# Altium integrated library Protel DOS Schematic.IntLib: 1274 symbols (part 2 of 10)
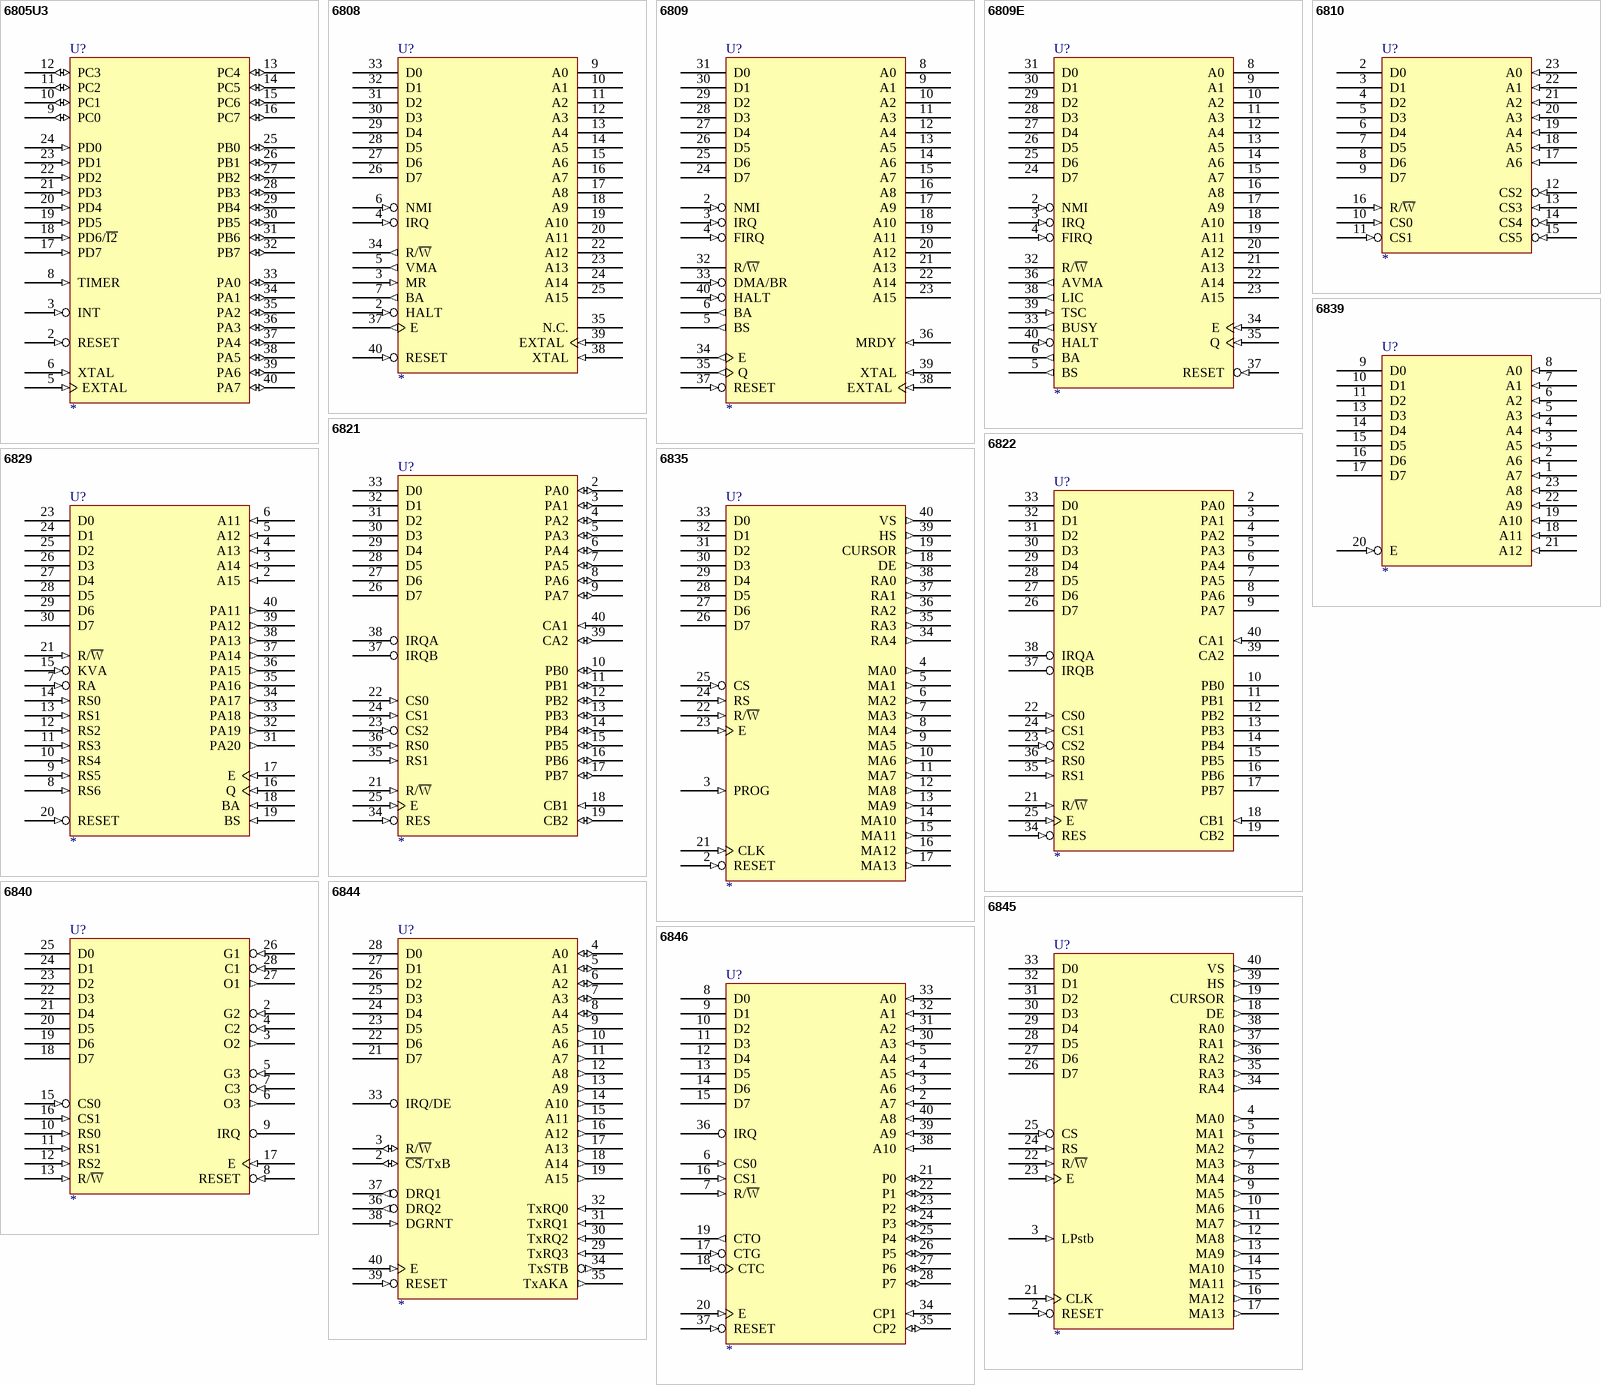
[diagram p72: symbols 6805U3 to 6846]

## 6810
designator U?
footprint DIP-24
pins: 1 GND (power) hidden to GND, 2 D0 (hiz), 3 D1 (hiz), 4 D2 (hiz), 5 D3 (hiz), 6 D4 (hiz), 7 D5 (hiz), 8 D6 (hiz), 9 D7 (hiz), 10 CS0 (in), 11 CS1 (in), 12 CS2 (in), 13 CS3 (in), 14 CS4 (in), 15 CS5 (in), 16 R/~{W} (in), 17 A6 (in), 18 A5 (in), 19 A4 (in), 20 A3 (in), 21 A2 (in), 22 A1 (in), 23 A0 (in), 24 VCC (power) hidden to VCC
2 alternate drawings of the same symbol

## 6821
designator U?
footprint DIP-40
pins: 1 GND (power) hidden to GND, 2 PA0 (io), 3 PA1 (io), 4 PA2 (io), 5 PA3 (io), 6 PA4 (io), 7 PA5 (io), 8 PA6 (io), 9 PA7 (io), 10 PB0 (io), 11 PB1 (io), 12 PB2 (io), 13 PB3 (io), 14 PB4 (io), 15 PB5 (io), 16 PB6 (io), 17 PB7 (io), 18 CB1 (in), 19 CB2 (io), 20 VCC (power) hidden to VCC, 21 R/~{W} (in), 22 CS0 (in), 23 CS2 (in), 24 CS1 (in), 25 E (in), 26 D7 (hiz), 27 D6 (hiz), 28 D5 (hiz), 29 D4 (hiz), 30 D3 (hiz), 31 D2 (hiz), 32 D1 (hiz), 33 D0 (hiz), 34 RES (in), 35 RS1 (in), 36 RS0 (in), 37 IRQB (oc), 38 IRQA (oc), 39 CA2 (io), 40 CA1 (in)
2 alternate drawings of the same symbol

## 6822
designator U?
footprint DIP-40
pins: 1 GND (power) hidden to GND, 2 PA0 (oc), 3 PA1 (oc), 4 PA2 (oc), 5 PA3 (oc), 6 PA4 (oc), 7 PA5 (oc), 8 PA6 (oc), 9 PA7 (oc), 10 PB0 (oc), 11 PB1 (oc), 12 PB2 (oc), 13 PB3 (oc), 14 PB4 (oc), 15 PB5 (oc), 16 PB6 (oc), 17 PB7 (oc), 18 CB1 (in), 19 CB2 (oc), 20 VCC (power) hidden to VCC, 21 R/~{W} (in), 22 CS0 (in), 23 CS2 (in), 24 CS1 (in), 25 E (in), 26 D7 (hiz), 27 D6 (hiz), 28 D5 (hiz), 29 D4 (hiz), 30 D3 (hiz), 31 D2 (hiz), 32 D1 (hiz), 33 D0 (hiz), 34 RES (in), 35 RS1 (in), 36 RS0 (in), 37 IRQB (oc), 38 IRQA (oc), 39 CA2 (oc), 40 CA1 (in)
2 alternate drawings of the same symbol

## 6829
designator U?
footprint DIP-40
pins: 1 GND (power) hidden to GND, 2 A15 (in), 3 A14 (in), 4 A13 (in), 5 A12 (in), 6 A11 (in), 7 RA (in), 8 RS6 (in), 9 RS5 (in), 10 RS4 (in), 11 RS3 (in), 12 RS2 (in), 13 RS1 (in), 14 RS0 (in), 15 KVA (in), 16 Q (in), 17 E (in), 18 BA (in), 19 BS (in), 20 RESET (in), 21 R/~{W} (in), 22 VCC (power) hidden to VCC, 23 D0 (hiz), 24 D1 (hiz), 25 D2 (hiz), 26 D3 (hiz), 27 D4 (hiz), 28 D5 (hiz), 29 D6 (hiz), 30 D7 (hiz), 31 PA20 (out), 32 PA19 (out), 33 PA18 (out), 34 PA17 (out), 35 PA16 (out), 36 PA15 (out), 37 PA14 (out), 38 PA13 (out), 39 PA12 (out), 40 PA11 (out)
2 alternate drawings of the same symbol

## 6835
designator U?
footprint DIP-40
pins: 1 GND (power) hidden to GND, 2 RESET (in), 3 PROG (in), 4 MA0 (out), 5 MA1 (out), 6 MA2 (out), 7 MA3 (out), 8 MA4 (out), 9 MA5 (out), 10 MA6 (out), 11 MA7 (out), 12 MA8 (out), 13 MA9 (out), 14 MA10 (out), 15 MA11 (out), 16 MA12 (out), 17 MA13 (out), 18 DE (out), 19 CURSOR (out), 20 VCC (power) hidden to VCC, 21 CLK (in), 22 R/~{W} (in), 23 E (in), 24 RS (in), 25 CS (in), 26 D7 (hiz), 27 D6 (hiz), 28 D5 (hiz), 29 D4 (hiz), 30 D3 (hiz), 31 D2 (hiz), 32 D1 (hiz), 33 D0 (hiz), 34 RA4 (out), 35 RA3 (out), 36 RA2 (out), 37 RA1 (out), 38 RA0 (out), 39 HS (out), 40 VS (out)
2 alternate drawings of the same symbol

## 6839
designator U?
footprint DIP-24
pins: 1 A7 (in), 2 A6 (in), 3 A5 (in), 4 A4 (in), 5 A3 (in), 6 A2 (in), 7 A1 (in), 8 A0 (in), 9 D0 (hiz), 10 D1 (hiz), 11 D2 (hiz), 12 GND (power) hidden to GND, 13 D3 (hiz), 14 D4 (hiz), 15 D5 (hiz), 16 D6 (hiz), 17 D7 (hiz), 18 A11 (in), 19 A10 (in), 20 E (in), 21 A12 (in), 22 A9 (in), 23 A8 (in), 24 VCC (power) hidden to VCC
2 alternate drawings of the same symbol

## 6840
designator U?
footprint DIP-28
pins: 1 GND (power) hidden to GND, 2 G2 (in), 3 O2 (out), 4 C2 (in), 5 G3 (in), 6 O3 (out), 7 C3 (in), 8 RESET (in), 9 IRQ (oc), 10 RS0 (in), 11 RS1 (in), 12 RS2 (in), 13 R/~{W} (in), 14 VCC (power) hidden to VCC, 15 CS0 (in), 16 CS1 (in), 17 E (in), 18 D7 (hiz), 19 D6 (hiz), 20 D5 (hiz), 21 D4 (hiz), 22 D3 (hiz), 23 D2 (hiz), 24 D1 (hiz), 25 D0 (hiz), 26 G1 (in), 27 O1 (out), 28 C1 (in)
2 alternate drawings of the same symbol

## 6844
designator U?
footprint DIP-40
pins: 1 GND (power) hidden to GND, 2 ~{CS}/TxB (io), 3 R/~{W} (io), 4 A0 (io), 5 A1 (io), 6 A2 (io), 7 A3 (io), 8 A4 (io), 9 A5 (out), 10 A6 (out), 11 A7 (out), 12 A8 (out), 13 A9 (out), 14 A10 (out), 15 A11 (out), 16 A12 (out), 17 A13 (out), 18 A14 (out), 19 A15 (out), 20 VCC (power) hidden to VCC, 21 D7 (hiz), 22 D6 (hiz), 23 D5 (hiz), 24 D4 (hiz), 25 D3 (hiz), 26 D2 (hiz), 27 D1 (hiz), 28 D0 (hiz), 29 TxRQ3 (in), 30 TxRQ2 (in), 31 TxRQ1 (in), 32 TxRQ0 (in), 33 IRQ/DE (oc), 34 TxSTB (out), 35 TxAKA (out), 36 DRQ2 (out), 37 DRQ1 (out), 38 DGRNT (in), 39 RESET (in), 40 E (in)
2 alternate drawings of the same symbol

## 6845
designator U?
footprint DIP-40
pins: 1 GND (power) hidden to GND, 2 RESET (in), 3 LPstb (in), 4 MA0 (out), 5 MA1 (out), 6 MA2 (out), 7 MA3 (out), 8 MA4 (out), 9 MA5 (out), 10 MA6 (out), 11 MA7 (out), 12 MA8 (out), 13 MA9 (out), 14 MA10 (out), 15 MA11 (out), 16 MA12 (out), 17 MA13 (out), 18 DE (out), 19 CURSOR (out), 20 VCC (power) hidden to VCC, 21 CLK (in), 22 R/~{W} (in), 23 E (in), 24 RS (in), 25 CS (in), 26 D7 (hiz), 27 D6 (hiz), 28 D5 (hiz), 29 D4 (hiz), 30 D3 (hiz), 31 D2 (hiz), 32 D1 (hiz), 33 D0 (hiz), 34 RA4 (out), 35 RA3 (out), 36 RA2 (out), 37 RA1 (out), 38 RA0 (out), 39 HS (out), 40 VS (out)
2 alternate drawings of the same symbol

## 6846
designator U?
footprint DIP-40
pins: 1 GND (power) hidden to GND, 2 A7 (in), 3 A6 (in), 4 A5 (in), 5 A4 (in), 6 CS0 (in), 7 R/~{W} (in), 8 D0 (hiz), 9 D1 (hiz), 10 D2 (hiz), 11 D3 (hiz), 12 D4 (hiz), 13 D5 (hiz), 14 D6 (hiz), 15 D7 (hiz), 16 CS1 (in), 17 CTG (in), 18 CTC (in), 19 CTO (out), 20 E (in), 21 P0 (io), 22 P1 (io), 23 P2 (io), 24 P3 (io), 25 P4 (io), 26 P5 (io), 27 P6 (io), 28 P7 (io), 29 VCC (power) hidden to VCC, 30 A3 (in), 31 A2 (in), 32 A1 (in), 33 A0 (in), 34 CP1 (in), 35 CP2 (io), 36 IRQ (oc), 37 RESET (in), 38 A10 (in), 39 A9 (in), 40 A8 (in)
2 alternate drawings of the same symbol

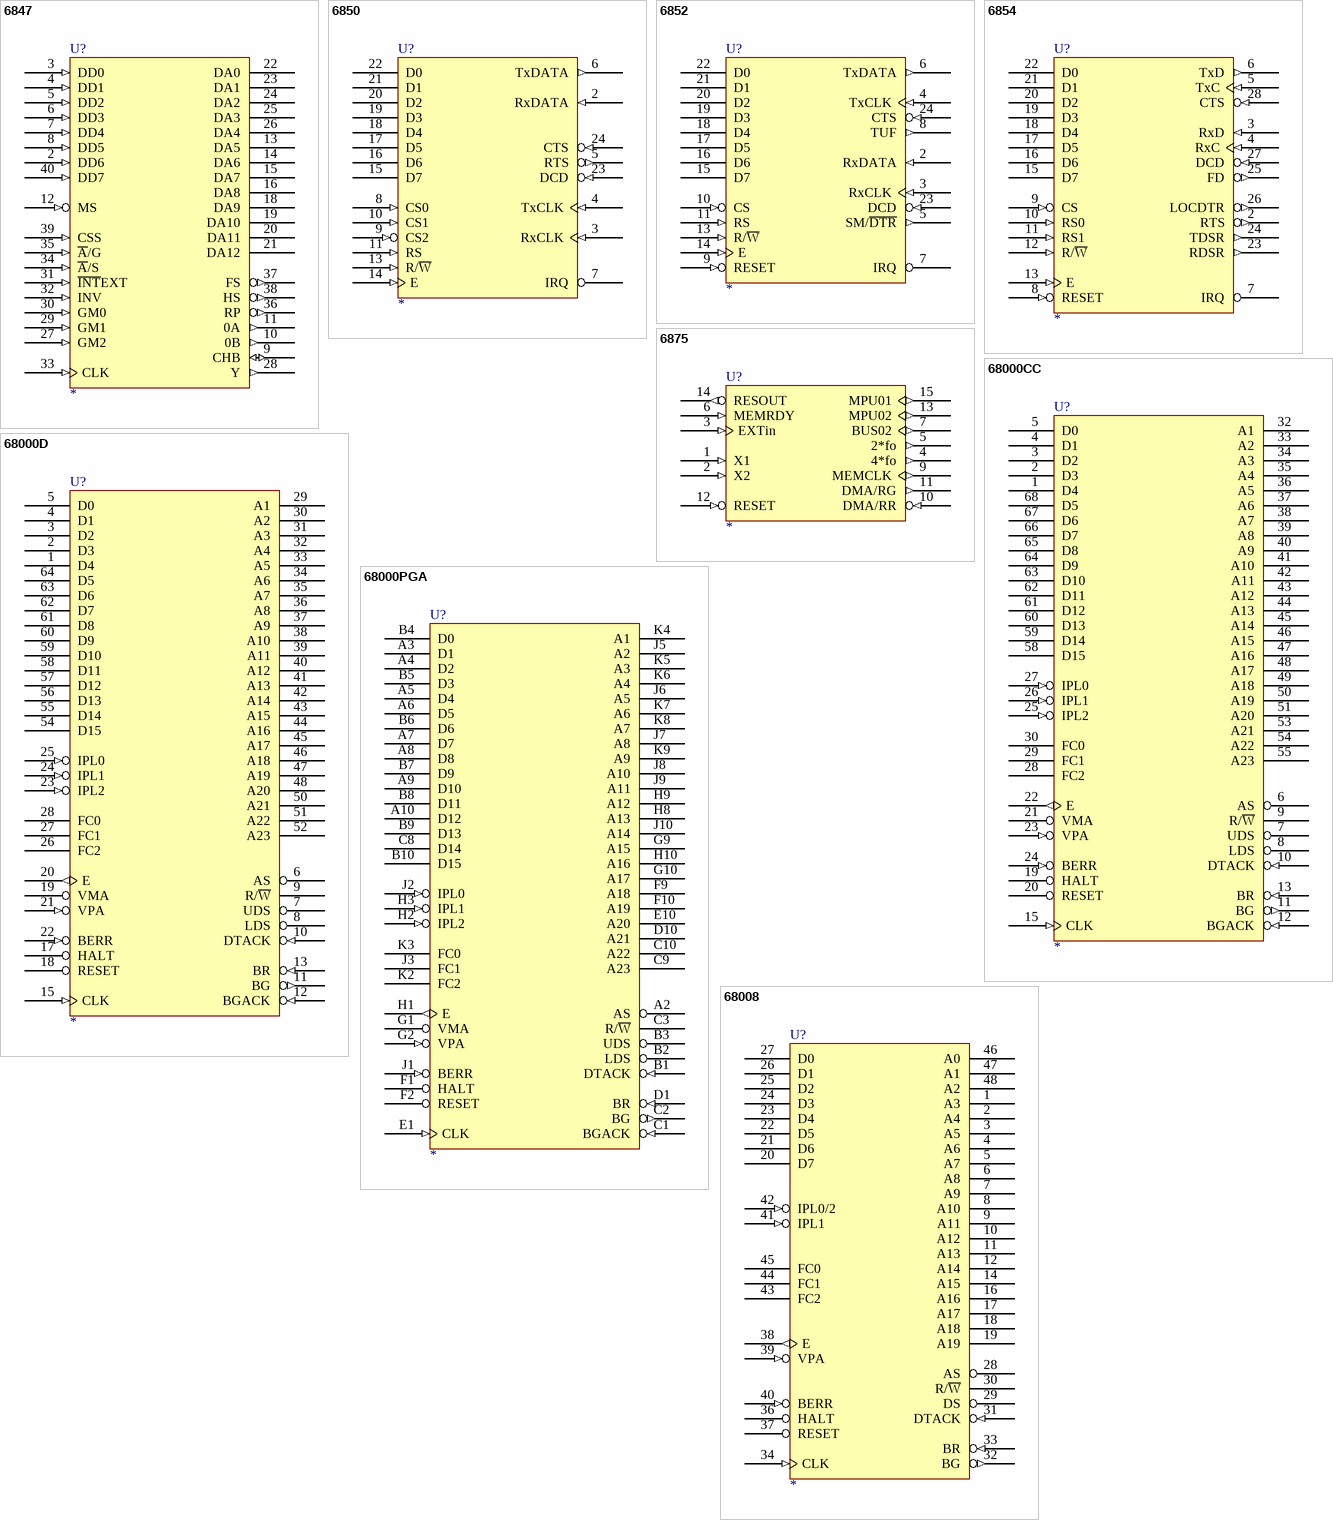
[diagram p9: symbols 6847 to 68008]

## 6847
designator U?
footprint DIP-40
pins: 1 GND (power) hidden to GND, 2 DD6 (in), 3 DD0 (in), 4 DD1 (in), 5 DD2 (in), 6 DD3 (in), 7 DD4 (in), 8 DD5 (in), 9 CHB (io), 10 0B (out), 11 0A (out), 12 MS (in), 13 DA5 (hiz), 14 DA6 (hiz), 15 DA7 (hiz), 16 DA8 (hiz), 17 VCC (power) hidden to VCC, 18 DA9 (hiz), 19 DA10 (hiz), 20 DA11 (hiz), 21 DA12 (hiz), 22 DA0 (hiz), 23 DA1 (hiz), 24 DA2 (hiz), 25 DA3 (hiz), 26 DA4 (hiz), 27 GM2 (in), 28 Y (out), 29 GM1 (in), 30 GM0 (in), 31 ~{INT}EXT (in), 32 INV (in), 33 CLK (in), 34 ~{A}/S (in), 35 ~{A}/G (in), 36 RP (out), 37 FS (out), 38 HS (out), 39 CSS (in), 40 DD7 (in)
2 alternate drawings of the same symbol

## 6850
designator U?
footprint DIP-24
pins: 1 GND (power) hidden to GND, 2 RxDATA (in), 3 RxCLK (in), 4 TxCLK (in), 5 RTS (out), 6 TxDATA (out), 7 IRQ (oc), 8 CS0 (in), 9 CS2 (in), 10 CS1 (in), 11 RS (in), 12 VCC (power) hidden to VCC, 13 R/~{W} (in), 14 E (in), 15 D7 (hiz), 16 D6 (hiz), 17 D5 (hiz), 18 D4 (hiz), 19 D3 (hiz), 20 D2 (hiz), 21 D1 (hiz), 22 D0 (hiz), 23 DCD (in), 24 CTS (in)
2 alternate drawings of the same symbol

## 6852
designator U?
footprint DIP-24
pins: 1 GND (power) hidden to GND, 2 RxDATA (in), 3 RxCLK (in), 4 TxCLK (in), 5 SM/~{DTR} (out), 6 TxDATA (out), 7 IRQ (oc), 8 TUF (out), 9 RESET (in), 10 CS (in), 11 RS (in), 12 VCC (power) hidden to VCC, 13 R/~{W} (in), 14 E (in), 15 D7 (hiz), 16 D6 (hiz), 17 D5 (hiz), 18 D4 (hiz), 19 D3 (hiz), 20 D2 (hiz), 21 D1 (hiz), 22 D0 (hiz), 23 DCD (in), 24 CTS (in)
2 alternate drawings of the same symbol

## 6854
designator U?
footprint DIP-28
pins: 1 GND (power) hidden to GND, 2 RTS (out), 3 RxD (in), 4 RxC (in), 5 TxC (in), 6 TxD (out), 7 IRQ (oc), 8 RESET (in), 9 CS (in), 10 RS0 (in), 11 RS1 (in), 12 R/~{W} (in), 13 E (in), 14 VCC (power) hidden to VCC, 15 D7 (hiz), 16 D6 (hiz), 17 D5 (hiz), 18 D4 (hiz), 19 D3 (hiz), 20 D2 (hiz), 21 D1 (hiz), 22 D0 (hiz), 23 RDSR (out), 24 TDSR (out), 25 FD (out), 26 LOCDTR (out), 27 DCD (in), 28 CTS (in)
2 alternate drawings of the same symbol

## 6875
designator U?
footprint DIP-16
pins: 1 X1 (in), 2 X2 (in), 3 EXTin (in), 4 4*fo (out), 5 2*fo (out), 6 MEMRDY (in), 7 BUS02 (out), 8 GND (power) hidden to GND, 9 MEMCLK (out), 10 DMA/RR (in), 11 DMA/RG (out), 12 RESET (in), 13 MPU02 (out), 14 RESOUT (out), 15 MPU01 (out), 16 VCC (power) hidden to VCC
2 alternate drawings of the same symbol

## 68000CC
designator U?
footprint JEDECA-68
pins: 1 D4 (hiz), 2 D3 (hiz), 3 D2 (hiz), 4 D1 (hiz), 5 D0 (hiz), 6 AS (hiz), 7 UDS (hiz), 8 LDS (hiz), 9 R/~{W} (hiz), 10 DTACK (in), 11 BG (out), 12 BGACK (in), 13 BR (in), 14 VCC (power) hidden to VCC, 15 CLK (in), 16 GND (power) hidden to GND, 17 GND (power) hidden to GND, 19 HALT (oc), 20 RESET (oc), 21 VMA (hiz), 22 E (out), 23 VPA (in), 24 BERR (in), 25 IPL2 (in), 26 IPL1 (in), 27 IPL0 (in), 28 FC2 (hiz), 29 FC1 (hiz), 30 FC0 (hiz), 32 A1 (hiz), 33 A2 (hiz), 34 A3 (hiz), 35 A4 (hiz), 36 A5 (hiz), 37 A6 (hiz), 38 A7 (hiz), 39 A8 (hiz), 40 A9 (hiz), 41 A10 (hiz), 42 A11 (hiz), 43 A12 (hiz), 44 A13 (hiz), 45 A14 (hiz), 46 A15 (hiz), 47 A16 (hiz), 48 A17 (hiz), 49 A18 (hiz), 50 A19 (hiz), 51 A20 (hiz), 52 VCC (power) hidden to VCC, 53 A21 (hiz), 54 A22 (hiz), 55 A23 (hiz), 56 GND (power) hidden to GND, 57 GND (power) hidden to GND, 58 D15 (hiz), 59 D14 (hiz), 60 D13 (hiz), 61 D12 (hiz), 62 D11 (hiz), 63 D10 (hiz), 64 D9 (hiz), 65 D8 (hiz), 66 D7 (hiz), 67 D6 (hiz), 68 D5 (hiz)
2 alternate drawings of the same symbol

## 68000D
designator U?
footprint DIP-64
pins: 1 D4 (hiz), 2 D3 (hiz), 3 D2 (hiz), 4 D1 (hiz), 5 D0 (hiz), 6 AS (hiz), 7 UDS (hiz), 8 LDS (hiz), 9 R/~{W} (hiz), 10 DTACK (in), 11 BG (out), 12 BGACK (in), 13 BR (in), 14 VCC (power) hidden to VCC, 15 CLK (in), 16 GND (power) hidden to GND, 17 HALT (oc), 18 RESET (oc), 19 VMA (hiz), 20 E (out), 21 VPA (in), 22 BERR (in), 23 IPL2 (in), 24 IPL1 (in), 25 IPL0 (in), 26 FC2 (hiz), 27 FC1 (hiz), 28 FC0 (hiz), 29 A1 (hiz), 30 A2 (hiz), 31 A3 (hiz), 32 A4 (hiz), 33 A5 (hiz), 34 A6 (hiz), 35 A7 (hiz), 36 A8 (hiz), 37 A9 (hiz), 38 A10 (hiz), 39 A11 (hiz), 40 A12 (hiz), 41 A13 (hiz), 42 A14 (hiz), 43 A15 (hiz), 44 A16 (hiz), 45 A17 (hiz), 46 A18 (hiz), 47 A19 (hiz), 48 A20 (hiz), 49 VCC (power) hidden to VCC, 50 A21 (hiz), 51 A22 (hiz), 52 A23 (hiz), 53 GND (power) hidden to GND, 54 D15 (hiz), 55 D14 (hiz), 56 D13 (hiz), 57 D12 (hiz), 58 D11 (hiz), 59 D10 (hiz), 60 D9 (hiz), 61 D8 (hiz), 62 D7 (hiz), 63 D6 (hiz), 64 D5 (hiz)
2 alternate drawings of the same symbol

## 68000PGA
designator U?
footprint PGA68_10X10
pins: A2 AS (hiz), A3 D1 (hiz), A4 D2 (hiz), A5 D4 (hiz), A6 D5 (hiz), A7 D7 (hiz), A8 D8 (hiz), A9 D10 (hiz), A10 D12 (hiz), B1 DTACK (in), B2 LDS (hiz), B3 UDS (hiz), B4 D0 (hiz), B5 D3 (hiz), B6 D6 (hiz), B7 D9 (hiz), B8 D11 (hiz), B9 D13 (hiz), B10 D15 (hiz), C1 BGACK (in), C2 BG (out), C3 R/~{W} (hiz), C8 D14 (hiz), C9 A23 (hiz), C10 A22 (hiz), D1 BR (in), D2 VCC (power) hidden to VCC, D9 GND (power) hidden to GND, D10 A21 (hiz), E1 CLK (in), E2 GND (power) hidden to GND, E9 VCC (power) hidden to VCC, E10 A20 (hiz), F1 HALT (oc), F2 RESET (oc), F9 A18 (hiz), F10 A19 (hiz), G1 VMA (hiz), G2 VPA (in), G9 A15 (hiz), G10 A17 (hiz), H1 E (out), H2 IPL2 (in), H3 IPL1 (in), H8 A13 (hiz), H9 A12 (hiz), H10 A16 (hiz), J1 BERR (in), J2 IPL0 (in), J3 FC1 (hiz), J5 A2 (hiz), J6 A5 (hiz), J7 A8 (hiz), J8 A10 (hiz), J9 A11 (hiz), J10 A14 (hiz), K2 FC2 (hiz), K3 FC0 (hiz), K4 A1 (hiz), K5 A3 (hiz), K6 A4 (hiz), K7 A6 (hiz), K8 A7 (hiz), K9 A9 (hiz)
2 alternate drawings of the same symbol

## 68008
designator U?
footprint DIP-48
pins: 1 A3 (hiz), 2 A4 (hiz), 3 A5 (hiz), 4 A6 (hiz), 5 A7 (hiz), 6 A8 (hiz), 7 A9 (hiz), 8 A10 (hiz), 9 A11 (hiz), 10 A12 (hiz), 11 A13 (hiz), 12 A14 (hiz), 13 VCC (power) hidden to VCC, 14 A15 (hiz), 15 GND (power) hidden to GND, 16 A16 (hiz), 17 A17 (hiz), 18 A18 (hiz), 19 A19 (hiz), 20 D7 (hiz), 21 D6 (hiz), 22 D5 (hiz), 23 D4 (hiz), 24 D3 (hiz), 25 D2 (hiz), 26 D1 (hiz), 27 D0 (hiz), 28 AS (hiz), 29 DS (hiz), 30 R/~{W} (hiz), 31 DTACK (in), 32 BG (out), 33 BR (in), 34 CLK (in), 35 GND (power) hidden to GND, 36 HALT (oc), 37 RESET (oc), 38 E (out), 39 VPA (in), 40 BERR (in), 41 IPL1 (in), 42 IPL0/2 (in), 43 FC2 (hiz), 44 FC1 (hiz), 45 FC0 (hiz), 46 A0 (hiz), 47 A1 (hiz), 48 A2 (hiz)
2 alternate drawings of the same symbol

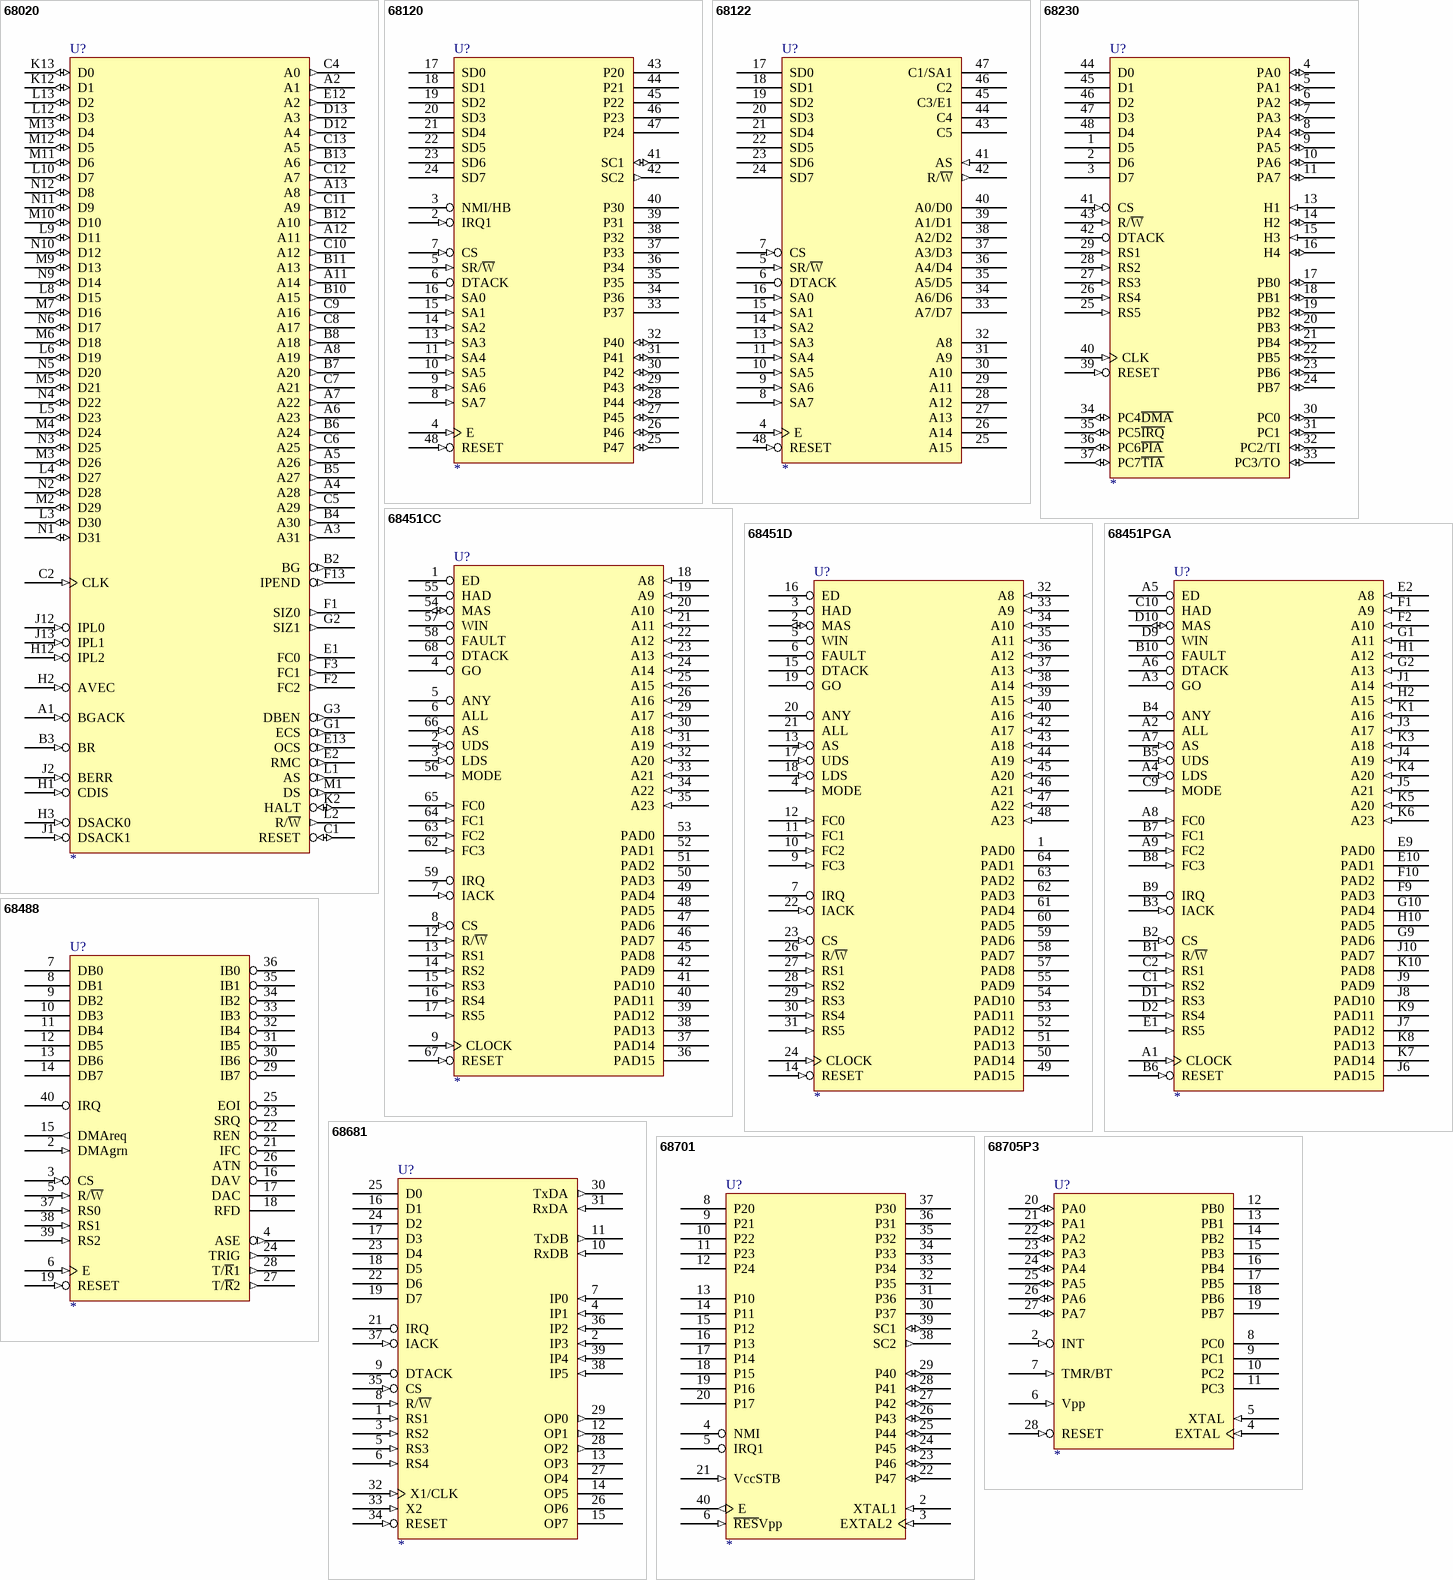
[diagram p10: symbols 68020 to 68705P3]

## 68020
designator U?
footprint PGA68_10X10
pins: A1 BGACK (in), A2 A1 (out), A3 A31 (out), A4 A28 (out), A5 A26 (out), A6 A23 (out), A7 A22 (out), A8 A19 (out), A9 VCC (power) hidden to VCC, A10 GND (power) hidden to GND, A11 A14 (out), A12 A11 (out), A13 A8 (out), B2 BG (out), B3 BR (in), B4 A30 (out), B5 A27 (out), B6 A24 (out), B7 A20 (out), B8 A18 (out), B9 GND (power) hidden to GND, B10 A15 (out), B11 A13 (out), B12 A10 (out), B13 A6 (out), C1 RESET (io), C2 CLK (in), C4 A0 (out), C5 A29 (out), C6 A25 (out), C7 A21 (out), C8 A17 (out), C9 A16 (out), C10 A12 (out), C11 A9 (out), C12 A7 (out), C13 A5 (out), D1 VCC (power) hidden to VCC, D2 VCC (power) hidden to VCC, D12 A4 (out), D13 A3 (out), E1 FC0 (out), E2 RMC (out), E3 VCC (power) hidden to VCC, E12 A2 (out), E13 OCS (out), F1 SIZ0 (out), F2 FC2 (out), F3 FC1 (out), F13 IPEND (out), G1 ECS (out), G2 SIZ1 (out), G3 DBEN (out), G11 VCC (power) hidden to VCC, G12 GND (power) hidden to GND, G13 VCC (power) hidden to VCC, H1 CDIS (in), H2 AVEC (in), H3 DSACK0 (in), H12 IPL2 (in), H13 GND (power) hidden to GND, J1 DSACK1 (in), J2 BERR (in), J3 GND (power) hidden to GND, J12 IPL0 (in), J13 IPL1 (in), K1 GND (power) hidden to GND, K2 HALT (io), K12 D1 (io), K13 D0 (io), L1 AS (out), L2 R/~{W} (out), L3 D30 (io), L4 D27 (io), L5 D23 (io), L6 D19 (io), L7 GND (power) hidden to GND, L8 D15 (io), L9 D11 (io), L10 D7 (io), L12 D3 (io), L13 D2 (io), M1 DS (out), M2 D29 (io), M3 D26 (io), M4 D24 (io), M5 D21 (io), M6 D18 (io), M7 D16 (io), M8 VCC (power) hidden to VCC, M9 D13 (io), M10 D10 (io), M11 D6 (io), M12 D5 (io), M13 D4 (io), N1 D31 (io), N2 D28 (io), N3 D25 (io), N4 D22 (io), N5 D20 (io), N6 D17 (io), N7 GND (power) hidden to GND, N8 VCC (power) hidden to VCC, N9 D14 (io), N10 D12 (io), N11 D9 (io), N12 D8 (io)
2 alternate drawings of the same symbol

## 68120
designator U?
footprint DIP-48
pins: 1 GND (power) hidden to GND, 2 IRQ1 (in), 3 NMI/HB (oc), 4 E (in), 5 SR/~{W} (in), 6 DTACK (oc), 7 CS (in), 8 SA7 (in), 9 SA6 (in), 10 SA5 (in), 11 SA4 (in), 12 VCC (power) hidden to VCC, 13 SA3 (in), 14 SA2 (in), 15 SA1 (in), 16 SA0 (in), 17 SD0 (hiz), 18 SD1 (hiz), 19 SD2 (hiz), 20 SD3 (hiz), 21 SD4 (hiz), 22 SD5 (hiz), 23 SD6 (hiz), 24 SD7 (hiz), 25 P47 (io), 26 P46 (io), 27 P45 (io), 28 P44 (io), 29 P43 (io), 30 P42 (io), 31 P41 (io), 32 P40 (io), 33 P37 (hiz), 34 P36 (hiz), 35 P35 (hiz), 36 P34 (hiz), 37 P33 (hiz), 38 P32 (hiz), 39 P31 (hiz), 40 P30 (hiz), 41 SC1 (io), 42 SC2 (out), 43 P20 (hiz), 44 P21 (hiz), 45 P22 (hiz), 46 P23 (hiz), 47 P24 (hiz), 48 RESET (in)
2 alternate drawings of the same symbol

## 68122
designator U?
footprint DIP-48
pins: 1 GND (power) hidden to GND, 2 VCC (power) hidden to VCC, 3 VCC (power) hidden to VCC, 4 E (in), 5 SR/~{W} (in), 6 DTACK (oc), 7 CS (in), 8 SA7 (in), 9 SA6 (in), 10 SA5 (in), 11 SA4 (in), 12 VCC (power) hidden to VCC, 13 SA3 (in), 14 SA2 (in), 15 SA1 (in), 16 SA0 (in), 17 SD0 (hiz), 18 SD1 (hiz), 19 SD2 (hiz), 20 SD3 (hiz), 21 SD4 (hiz), 22 SD5 (hiz), 23 SD6 (hiz), 24 SD7 (hiz), 25 A15 (hiz), 26 A14 (hiz), 27 A13 (hiz), 28 A12 (hiz), 29 A11 (hiz), 30 A10 (hiz), 31 A9 (hiz), 32 A8 (hiz), 33 A7/D7 (hiz), 34 A6/D6 (hiz), 35 A5/D5 (hiz), 36 A4/D4 (hiz), 37 A3/D3 (hiz), 38 A2/D2 (hiz), 39 A1/D1 (hiz), 40 A0/D0 (hiz), 41 AS (in), 42 R/~{W} (out), 43 C5 (hiz), 44 C4 (hiz), 45 C3/E1 (hiz), 46 C2 (hiz), 47 C1/SA1 (hiz), 48 RESET (in)
2 alternate drawings of the same symbol

## 68230
designator U?
footprint DIP-48
pins: 1 D5 (hiz), 2 D6 (hiz), 3 D7 (hiz), 4 PA0 (io), 5 PA1 (io), 6 PA2 (io), 7 PA3 (io), 8 PA4 (io), 9 PA5 (io), 10 PA6 (io), 11 PA7 (io), 12 VCC (power) hidden to VCC, 13 H1 (in), 14 H2 (io), 15 H3 (in), 16 H4 (io), 17 PB0 (io), 18 PB1 (io), 19 PB2 (io), 20 PB3 (io), 21 PB4 (io), 22 PB5 (io), 23 PB6 (io), 24 PB7 (io), 25 RS5 (in), 26 RS4 (in), 27 RS3 (in), 28 RS2 (in), 29 RS1 (in), 30 PC0 (io), 31 PC1 (io), 32 PC2/TI (io), 33 PC3/TO (io), 34 PC4~{DMA} (io), 35 PC5~{IRQ} (io), 36 PC6~{PIA} (io), 37 PC7~{TIA} (io), 38 GND (power) hidden to GND, 39 RESET (in), 40 CLK (in), 41 CS (in), 42 DTACK (oc), 43 R/~{W} (in), 44 D0 (hiz), 45 D1 (hiz), 46 D2 (hiz), 47 D3 (hiz), 48 D4 (hiz)
2 alternate drawings of the same symbol

## 68451CC
designator U?
footprint JEDECA-68
pins: 1 ED (hiz), 2 UDS (in), 3 LDS (in), 4 GO (oc), 5 ANY (oc), 6 ALL (oc), 7 IACK (in), 8 CS (in), 9 CLOCK (in), 10 VCC (power) hidden to VCC, 11 VCC (power) hidden to VCC, 12 R/~{W} (in), 13 RS1 (in), 14 RS2 (in), 15 RS3 (in), 16 RS4 (in), 17 RS5 (in), 18 A8 (in), 19 A9 (in), 20 A10 (in), 21 A11 (in), 22 A12 (in), 23 A13 (in), 24 A14 (in), 25 A15 (in), 26 A16 (in), 27 GND (power) hidden to GND, 28 GND (power) hidden to GND, 29 A17 (in), 30 A18 (in), 31 A19 (in), 32 A20 (in), 33 A21 (in), 34 A22 (in), 35 A23 (in), 36 PAD15 (hiz), 37 PAD14 (hiz), 38 PAD13 (hiz), 39 PAD12 (hiz), 40 PAD11 (hiz), 41 PAD10 (hiz), 42 PAD9 (hiz), 43 VCC (power) hidden to VCC, 44 VCC (power) hidden to VCC, 45 PAD8 (hiz), 46 PAD7 (hiz), 47 PAD6 (hiz), 48 PAD5 (hiz), 49 PAD4 (hiz), 50 PAD3 (hiz), 51 PAD2 (hiz), 52 PAD1 (hiz), 53 PAD0 (hiz), 54 MAS (io), 55 HAD (hiz), 56 MODE (in), 57 WIN (hiz), 58 FAULT (oc), 59 IRQ (oc), 60 GND (power) hidden to GND, 61 GND (power) hidden to GND, 62 FC3 (in), 63 FC2 (in), 64 FC1 (in), 65 FC0 (in), 66 AS (in), 67 RESET (in), 68 DTACK (hiz)
2 alternate drawings of the same symbol

## 68451D
designator U?
footprint DIP-64
pins: 1 PAD0 (hiz), 2 MAS (io), 3 HAD (hiz), 4 MODE (in), 5 WIN (hiz), 6 FAULT (oc), 7 IRQ (oc), 8 GND (power) hidden to GND, 9 FC3 (in), 10 FC2 (in), 11 FC1 (in), 12 FC0 (in), 13 AS (in), 14 RESET (in), 15 DTACK (hiz), 16 ED (hiz), 17 UDS (in), 18 LDS (in), 19 GO (oc), 20 ANY (oc), 21 ALL (oc), 22 IACK (in), 23 CS (in), 24 CLOCK (in), 25 VCC (power) hidden to VCC, 26 R/~{W} (in), 27 RS1 (in), 28 RS2 (in), 29 RS3 (in), 30 RS4 (in), 31 RS5 (in), 32 A8 (in), 33 A9 (in), 34 A10 (in), 35 A11 (in), 36 A12 (in), 37 A13 (in), 38 A14 (in), 39 A15 (in), 40 A16 (in), 41 GND (power) hidden to GND, 42 A17 (in), 43 A18 (in), 44 A19 (in), 45 A20 (in), 46 A21 (in), 47 A22 (in), 48 A23 (in), 49 PAD15 (hiz), 50 PAD14 (hiz), 51 PAD13 (hiz), 52 PAD12 (hiz), 53 PAD11 (hiz), 54 PAD10 (hiz), 55 PAD9 (hiz), 56 VCC (power) hidden to VCC, 57 PAD8 (hiz), 58 PAD7 (hiz), 59 PAD6 (hiz), 60 PAD5 (hiz), 61 PAD4 (hiz), 62 PAD3 (hiz), 63 PAD2 (hiz), 64 PAD1 (hiz)
2 alternate drawings of the same symbol

## 68451PGA
designator U?
footprint PGA68_10X10
pins: A1 CLOCK (in), A2 ALL (oc), A3 GO (oc), A4 LDS (in), A5 ED (hiz), A6 DTACK (hiz), A7 AS (in), A8 FC0 (in), A9 FC2 (in), A10 GND (power) hidden to GND, B1 R/~{W} (in), B2 CS (in), B3 IACK (in), B4 ANY (oc), B5 UDS (in), B6 RESET (in), B7 FC1 (in), B8 FC3 (in), B9 IRQ (oc), B10 FAULT (oc), C1 RS2 (in), C2 RS1 (in), C3 VCC (power) hidden to VCC, C8 GND (power) hidden to GND, C9 MODE (in), C10 HAD (hiz), D1 RS3 (in), D2 RS4 (in), D9 WIN (hiz), D10 MAS (io), E1 RS5 (in), E2 A8 (in), E9 PAD0 (hiz), E10 PAD1 (hiz), F1 A9 (in), F2 A10 (in), F9 PAD3 (hiz), F10 PAD2 (hiz), G1 A11 (in), G2 A13 (in), G9 PAD6 (hiz), G10 PAD4 (hiz), H1 A12 (in), H2 A15 (in), H3 GND (power) hidden to GND, H8 VCC (power) hidden to VCC, H9 VCC (power) hidden to VCC, H10 PAD5 (hiz), J1 A14 (in), J2 GND (power) hidden to GND, J3 A17 (in), J4 A19 (in), J5 A21 (in), J6 PAD15 (hiz), J7 PAD12 (hiz), J8 PAD10 (hiz), J9 PAD9 (hiz), J10 PAD7 (hiz), K1 A16 (in), K3 A18 (in), K4 A20 (in), K5 A20 (in), K6 A23 (in), K7 PAD14 (hiz), K8 PAD13 (hiz), K9 PAD11 (hiz), K10 PAD8 (hiz)
2 alternate drawings of the same symbol

## 68488
designator U?
footprint DIP-40
pins: 1 GND (power) hidden to GND, 2 DMAgrn (in), 3 CS (in), 4 ASE (out), 5 R/~{W} (in), 6 E (in), 7 DB0 (hiz), 8 DB1 (hiz), 9 DB2 (hiz), 10 DB3 (hiz), 11 DB4 (hiz), 12 DB5 (hiz), 13 DB6 (hiz), 14 DB7 (hiz), 15 DMAreq (out), 16 DAV (hiz), 17 DAC (hiz), 18 RFD (hiz), 19 RESET (in), 20 VCC (power) hidden to VCC, 21 IFC (hiz), 22 REN (hiz), 23 SRQ (oc), 24 TRIG (out), 25 EOI (hiz), 26 ATN (hiz), 27 T/~{R}2 (out), 28 T/~{R}1 (out), 29 IB7 (hiz), 30 IB6 (hiz), 31 IB5 (hiz), 32 IB4 (hiz), 33 IB3 (hiz), 34 IB2 (hiz), 35 IB1 (hiz), 36 IB0 (hiz), 37 RS0 (in), 38 RS1 (in), 39 RS2 (in), 40 IRQ (oc)
2 alternate drawings of the same symbol

## 68681
designator U?
footprint DIP-40
pins: 1 RS1 (in), 2 IP3 (in), 3 RS2 (in), 4 IP1 (in), 5 RS3 (in), 6 RS4 (in), 7 IP0 (in), 8 R/~{W} (in), 9 DTACK (hiz), 10 RxDB (in), 11 TxDB (out), 12 OP1 (out), 13 OP3 (oc), 14 OP5 (oc), 15 OP7 (oc), 16 D1 (hiz), 17 D3 (hiz), 18 D5 (hiz), 19 D7 (hiz), 20 GND (power) hidden to GND, 21 IRQ (oc), 22 D6 (hiz), 23 D4 (hiz), 24 D2 (hiz), 25 D0 (hiz), 26 OP6 (oc), 27 OP4 (oc), 28 OP2 (out), 29 OP0 (out), 30 TxDA (out), 31 RxDA (in), 32 X1/CLK (in), 33 X2 (in), 34 RESET (in), 35 CS (in), 36 IP2 (in), 37 IACK (in), 38 IP5 (in), 39 IP4 (in), 40 VCC (power) hidden to VCC
2 alternate drawings of the same symbol

## 68701
designator U?
footprint DIP-40
pins: 1 GND (power) hidden to GND, 2 XTAL1 (in), 3 EXTAL2 (in), 4 NMI (oc), 5 IRQ1 (oc), 6 ~{RES}Vpp (in), 7 VCC (power) hidden to VCC, 8 P20 (hiz), 9 P21 (hiz), 10 P22 (hiz), 11 P23 (hiz), 12 P24 (hiz), 13 P10 (hiz), 14 P11 (hiz), 15 P12 (hiz), 16 P13 (hiz), 17 P14 (hiz), 18 P15 (hiz), 19 P16 (hiz), 20 P17 (hiz), 21 VccSTB (in), 22 P47 (io), 23 P46 (io), 24 P45 (io), 25 P44 (io), 26 P43 (io), 27 P42 (io), 28 P41 (io), 29 P40 (io), 30 P37 (hiz), 31 P36 (hiz), 32 P35 (hiz), 33 P34 (hiz), 34 P33 (hiz), 35 P32 (hiz), 36 P31 (hiz), 37 P30 (hiz), 38 SC2 (out), 39 SC1 (io), 40 E (out)
2 alternate drawings of the same symbol

## 68705P3
designator U?
footprint DIP-28
pins: 1 GND (power) hidden to GND, 2 INT (in), 3 VCC (power) hidden to VCC, 4 EXTAL (in), 5 XTAL (in), 6 Vpp (in), 7 TMR/BT (in), 8 PC0 (hiz), 9 PC1 (hiz), 10 PC2 (hiz), 11 PC3 (hiz), 12 PB0 (hiz), 13 PB1 (hiz), 14 PB2 (hiz), 15 PB3 (hiz), 16 PB4 (hiz), 17 PB5 (hiz), 18 PB6 (hiz), 19 PB7 (hiz), 20 PA0 (io), 21 PA1 (io), 22 PA2 (io), 23 PA3 (io), 24 PA4 (io), 25 PA5 (io), 26 PA6 (io), 27 PA7 (io), 28 RESET (in)
2 alternate drawings of the same symbol

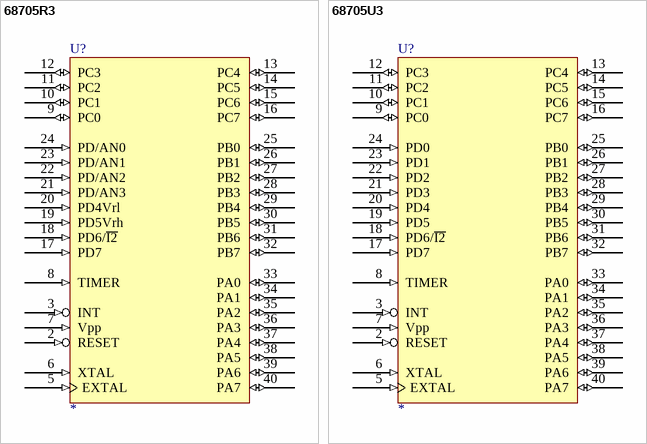
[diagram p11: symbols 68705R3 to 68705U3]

## 68705R3
designator U?
footprint DIP-40
pins: 1 GND (power) hidden to GND, 2 RESET (in), 3 INT (in), 4 VCC (power) hidden to VCC, 5 EXTAL (in), 6 XTAL (in), 7 Vpp (in), 8 TIMER (in), 9 PC0 (io), 10 PC1 (io), 11 PC2 (io), 12 PC3 (io), 13 PC4 (io), 14 PC5 (io), 15 PC6 (io), 16 PC7 (io), 17 PD7 (in), 18 PD6/~{I2} (in), 19 PD5Vrh (in), 20 PD4Vrl (in), 21 PD/AN3 (in), 22 PD/AN2 (in), 23 PD/AN1 (in), 24 PD/AN0 (in), 25 PB0 (io), 26 PB1 (io), 27 PB2 (io), 28 PB3 (io), 29 PB4 (io), 30 PB5 (io), 31 PB6 (io), 32 PB7 (io), 33 PA0 (io), 34 PA1 (io), 35 PA2 (io), 36 PA3 (io), 37 PA4 (io), 38 PA5 (io), 39 PA6 (io), 40 PA7 (io)
2 alternate drawings of the same symbol

## 68705U3
designator U?
footprint DIP-40
pins: 1 GND (power) hidden to GND, 2 RESET (in), 3 INT (in), 4 VCC (power) hidden to VCC, 5 EXTAL (in), 6 XTAL (in), 7 Vpp (in), 8 TIMER (in), 9 PC0 (io), 10 PC1 (io), 11 PC2 (io), 12 PC3 (io), 13 PC4 (io), 14 PC5 (io), 15 PC6 (io), 16 PC7 (io), 17 PD7 (in), 18 PD6/~{I2} (in), 19 PD5 (in), 20 PD4 (in), 21 PD3 (in), 22 PD2 (in), 23 PD1 (in), 24 PD0 (in), 25 PB0 (io), 26 PB1 (io), 27 PB2 (io), 28 PB3 (io), 29 PB4 (io), 30 PB5 (io), 31 PB6 (io), 32 PB7 (io), 33 PA0 (io), 34 PA1 (io), 35 PA2 (io), 36 PA3 (io), 37 PA4 (io), 38 PA5 (io), 39 PA6 (io), 40 PA7 (io)
2 alternate drawings of the same symbol


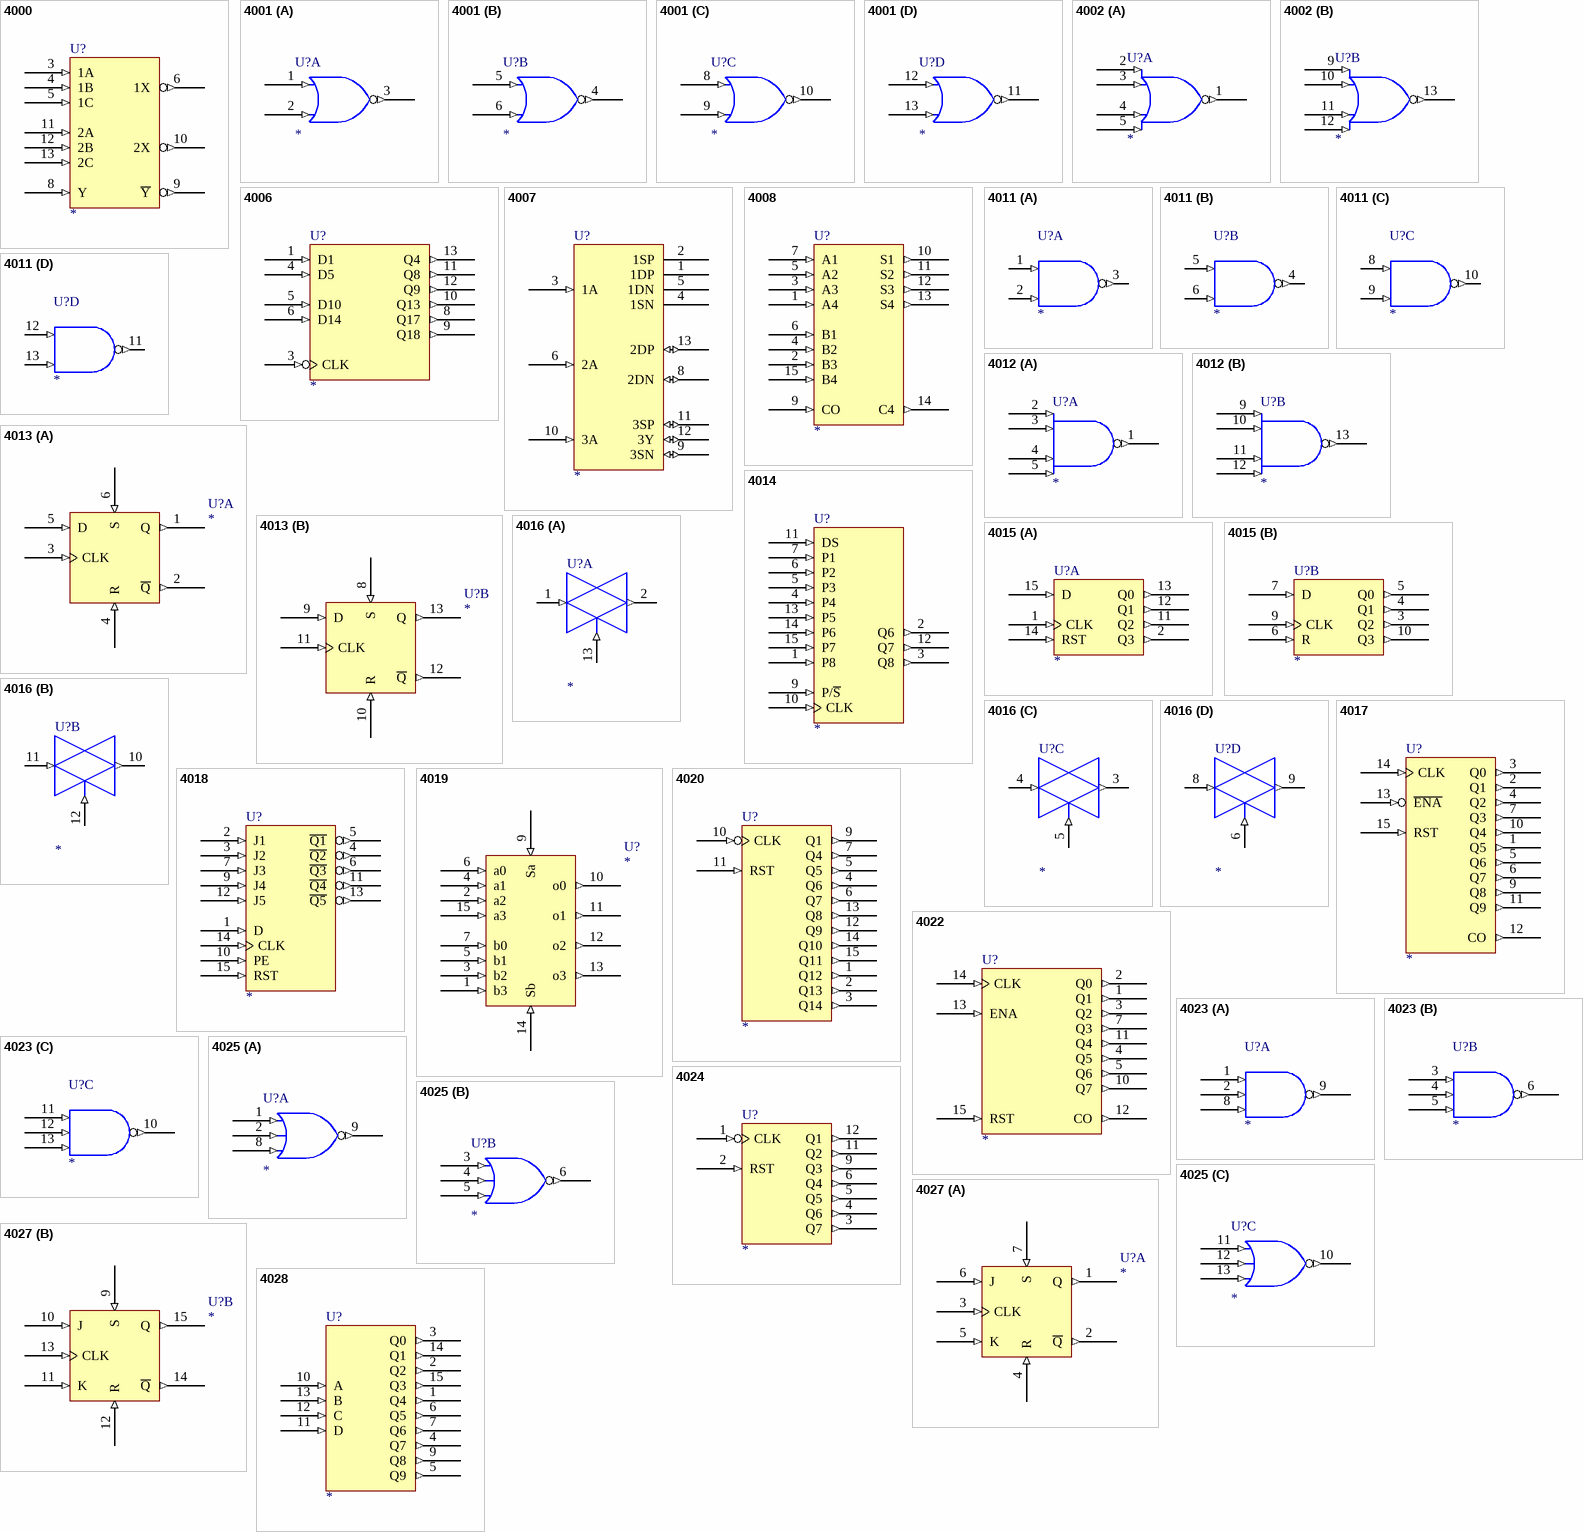
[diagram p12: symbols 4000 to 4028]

## 4000
designator U?
footprint DIP-14
pins: 3 1A (in), 4 1B (in), 5 1C (in), 6 1X (out), 7 GND (power) hidden to GND, 8 Y (in), 9 ~{Y} (out), 10 2X (out), 11 2A (in), 12 2B (in), 13 2C (in), 14 VCC (power) hidden to VCC
2 alternate drawings of the same symbol

## 4001
designator U?
footprint DIP-14
part A pins: 1 (in), 2 (in), 3 (out), 7 GND (power) hidden to GND, 14 VCC (power) hidden to VCC
part B pins: 4 (out), 5 (in), 6 (in), 7 GND (power) hidden to GND, 14 VCC (power) hidden to VCC
part C pins: 7 GND (power) hidden to GND, 8 (in), 9 (in), 10 (out), 14 VCC (power) hidden to VCC
part D pins: 7 GND (power) hidden to GND, 11 (out), 12 (in), 13 (in), 14 VCC (power) hidden to VCC
2 alternate drawings of the same symbol

## 4002
designator U?
footprint DIP-14
part A pins: 1 (out), 2 (in), 3 (in), 4 (in), 5 (in), 7 GND (power) hidden to GND, 14 VCC (power) hidden to VCC
part B pins: 7 GND (power) hidden to GND, 9 (in), 10 (in), 11 (in), 12 (in), 13 (out), 14 VCC (power) hidden to VCC
2 alternate drawings of the same symbol

## 4006
designator U?
footprint DIP-14
pins: 1 D1 (in), 3 CLK (in), 4 D5 (in), 5 D10 (in), 6 D14 (in), 7 GND (power) hidden to GND, 8 Q17 (out), 9 Q18 (out), 10 Q13 (out), 11 Q8 (out), 12 Q9 (out), 13 Q4 (out), 14 VCC (power) hidden to VCC
2 alternate drawings of the same symbol

## 4007
designator U?
footprint DIP-14
pins: 1 1DP (oc), 2 1SP (oc), 3 1A (in), 4 1SN (oc), 5 1DN (oc), 6 2A (in), 7 GND (in) hidden to GND, 8 2DN (io), 9 3SN (io), 10 3A (in), 11 3SP (io), 12 3Y (io), 13 2DP (io), 14 VCC (in) hidden to VCC
2 alternate drawings of the same symbol

## 4008
designator U?
footprint DIP-16
pins: 1 A4 (in), 2 B3 (in), 3 A3 (in), 4 B2 (in), 5 A2 (in), 6 B1 (in), 7 A1 (in), 8 GND (power) hidden to GND, 9 CO (in), 10 S1 (out), 11 S2 (out), 12 S3 (out), 13 S4 (out), 14 C4 (out), 15 B4 (in), 16 VCC (power) hidden to VCC
2 alternate drawings of the same symbol

## 4011
designator U?
footprint DIP14E
footprint DIP-14
part A pins: 1 (in), 2 (in), 3 (out), 7 GND (power) hidden to GND, 14 VCC (power) hidden to VCC
part B pins: 4 (out), 5 (in), 6 (in), 7 GND (power) hidden to GND, 14 VCC (power) hidden to VCC
part C pins: 7 GND (power) hidden to GND, 8 (in), 9 (in), 10 (out), 14 VCC (power) hidden to VCC
part D pins: 7 GND (power) hidden to GND, 11 (out), 12 (in), 13 (in), 14 VCC (power) hidden to VCC
2 alternate drawings of the same symbol

## 4012
designator U?
footprint DIP-14
part A pins: 1 (out), 2 (in), 3 (in), 4 (in), 5 (in), 7 GND (power) hidden to GND, 14 VCC (power) hidden to VCC
part B pins: 7 GND (power) hidden to GND, 9 (in), 10 (in), 11 (in), 12 (in), 13 (out), 14 VCC (power) hidden to VCC
2 alternate drawings of the same symbol

## 4013
designator U?
footprint DIP14E
part A pins: 1 Q (out), 2 ~{Q} (out), 3 CLK (in), 4 R (in), 5 D (in), 6 S (in), 7 GND (power) hidden to GND, 14 VCC (power) hidden to VCC
part B pins: 7 GND (power) hidden to GND, 8 S (in), 9 D (in), 10 R (in), 11 CLK (in), 12 ~{Q} (out), 13 Q (out), 14 VCC (power) hidden to VCC
2 alternate drawings of the same symbol

## 4014
designator U?
footprint DIP-16
pins: 1 P8 (in), 2 Q6 (out), 3 Q8 (out), 4 P4 (in), 5 P3 (in), 6 P2 (in), 7 P1 (in), 8 GND (power) hidden to GND, 9 P/~{S} (in), 10 CLK (in), 11 DS (in), 12 Q7 (out), 13 P5 (in), 14 P6 (in), 15 P7 (in), 16 VCC (power) hidden to VCC
2 alternate drawings of the same symbol

## 4015
designator U?
footprint DIP-16
part A pins: 1 CLK (in), 2 Q3 (out), 8 GND (power) hidden to GND, 11 Q2 (out), 12 Q1 (out), 13 Q0 (out), 14 RST (in), 15 D (in), 16 VCC (power) hidden to VCC
part B pins: 3 Q2 (out), 4 Q1 (out), 5 Q0 (out), 6 R (in), 7 D (in), 8 GND (power) hidden to GND, 9 CLK (in), 10 Q3 (out), 16 VCC (power) hidden to VCC
2 alternate drawings of the same symbol

## 4016
designator U?
footprint DIP14E
part A pins: 1 (in), 2 (out), 7 GND (power) hidden to GND, 13 (in), 14 VCC (power) hidden to VCC
part B pins: 7 GND (power) hidden to GND, 10 (out), 11 (in), 12 (in), 14 VCC (power) hidden to VCC
part C pins: 3 (out), 4 (in), 5 (in), 7 GND (power) hidden to GND, 14 VCC (power) hidden to VCC
part D pins: 6 (in), 7 GND (power) hidden to GND, 8 (in), 9 (out), 14 VCC (power) hidden to VCC
2 alternate drawings of the same symbol

## 4017
designator U?
footprint DIP-16
pins: 1 Q5 (out), 2 Q1 (out), 3 Q0 (out), 4 Q2 (out), 5 Q6 (out), 6 Q7 (out), 7 Q3 (out), 8 GND (power) hidden to GND, 9 Q8 (out), 10 Q4 (out), 11 Q9 (out), 12 CO (out), 13 ~{ENA} (in), 14 CLK (in), 15 RST (in), 16 VCC (power) hidden to VCC
2 alternate drawings of the same symbol

## 4018
designator U?
footprint DIP-16
pins: 1 D (in), 2 J1 (in), 3 J2 (in), 4 ~{Q2} (out), 5 ~{Q1} (out), 6 ~{Q3} (out), 7 J3 (in), 8 GND (power) hidden to GND, 9 J4 (in), 10 PE (in), 11 ~{Q4} (out), 12 J5 (in), 13 ~{Q5} (out), 14 CLK (in), 15 RST (in), 16 VCC (power) hidden to VCC
2 alternate drawings of the same symbol

## 4019
designator U?
footprint DIP-16
pins: 1 b3 (in), 2 a2 (in), 3 b2 (in), 4 a1 (in), 5 b1 (in), 6 a0 (in), 7 b0 (in), 8 GND (power) hidden to GND, 9 Sa (in), 10 o0 (out), 11 o1 (out), 12 o2 (out), 13 o3 (out), 14 Sb (in), 15 a3 (in), 16 VCC (power) hidden to VCC
2 alternate drawings of the same symbol

## 4020
designator U?
footprint DIP-16
pins: 1 Q12 (out), 2 Q13 (out), 3 Q14 (out), 4 Q6 (out), 5 Q5 (out), 6 Q7 (out), 7 Q4 (out), 8 GND (power) hidden to GND, 9 Q1 (out), 10 CLK (in), 11 RST (in), 12 Q9 (out), 13 Q8 (out), 14 Q10 (out), 15 Q11 (out), 16 VCC (power) hidden to VCC
2 alternate drawings of the same symbol

## 4022
designator U?
footprint DIP-16
pins: 1 Q1 (out), 2 Q0 (out), 3 Q2 (out), 4 Q5 (out), 5 Q6 (out), 7 Q3 (out), 8 GND (power) hidden to GND, 10 Q7 (out), 11 Q4 (out), 12 CO (out), 13 ENA (in), 14 CLK (in), 15 RST (in), 16 VCC (power) hidden to VCC
2 alternate drawings of the same symbol

## 4023
designator U?
footprint DIP-14
part A pins: 1 (in), 2 (in), 7 GND (power) hidden to GND, 8 (in), 9 (out), 14 VCC (power) hidden to VCC
part B pins: 3 (in), 4 (in), 5 (in), 6 (out), 7 GND (power) hidden to GND, 14 VCC (power) hidden to VCC
part C pins: 7 GND (power) hidden to GND, 10 (out), 11 (in), 12 (in), 13 (in), 14 VCC (power) hidden to VCC
2 alternate drawings of the same symbol

## 4024
designator U?
footprint DIP-14
pins: 1 CLK (in), 2 RST (in), 3 Q7 (out), 4 Q6 (out), 5 Q5 (out), 6 Q4 (out), 7 GND (power) hidden to GND, 9 Q3 (out), 11 Q2 (out), 12 Q1 (out), 14 VCC (power) hidden to VCC
2 alternate drawings of the same symbol

## 4025
designator U?
footprint DIP-14
part A pins: 1 (in), 2 (in), 7 GND (power) hidden to GND, 8 (in), 9 (out), 14 VCC (power) hidden to VCC
part B pins: 3 (in), 4 (in), 5 (in), 6 (out), 7 GND (power) hidden to GND, 14 VCC (power) hidden to VCC
part C pins: 7 GND (power) hidden to GND, 10 (out), 11 (in), 12 (in), 13 (in), 14 VCC (power) hidden to VCC
2 alternate drawings of the same symbol

## 4027
designator U?
footprint DIP-16
part A pins: 1 Q (out), 2 ~{Q} (out), 3 CLK (in), 4 R (in), 5 K (in), 6 J (in), 7 S (in), 16 VCC (power) hidden to VCC
part B pins: 9 S (in), 10 J (in), 11 K (in), 12 R (in), 13 CLK (in), 14 ~{Q} (out), 15 Q (out), 16 VCC (power) hidden to VCC
2 alternate drawings of the same symbol

## 4028
designator U?
footprint DIP16E
pins: 1 Q4 (out), 2 Q2 (out), 3 Q0 (out), 4 Q7 (out), 5 Q9 (out), 6 Q5 (out), 7 Q6 (out), 8 GND (power) hidden to GND, 9 Q8 (out), 10 A (in), 11 D (in), 12 C (in), 13 B (in), 14 Q1 (out), 15 Q3 (out), 16 VCC (power) hidden to VCC
2 alternate drawings of the same symbol

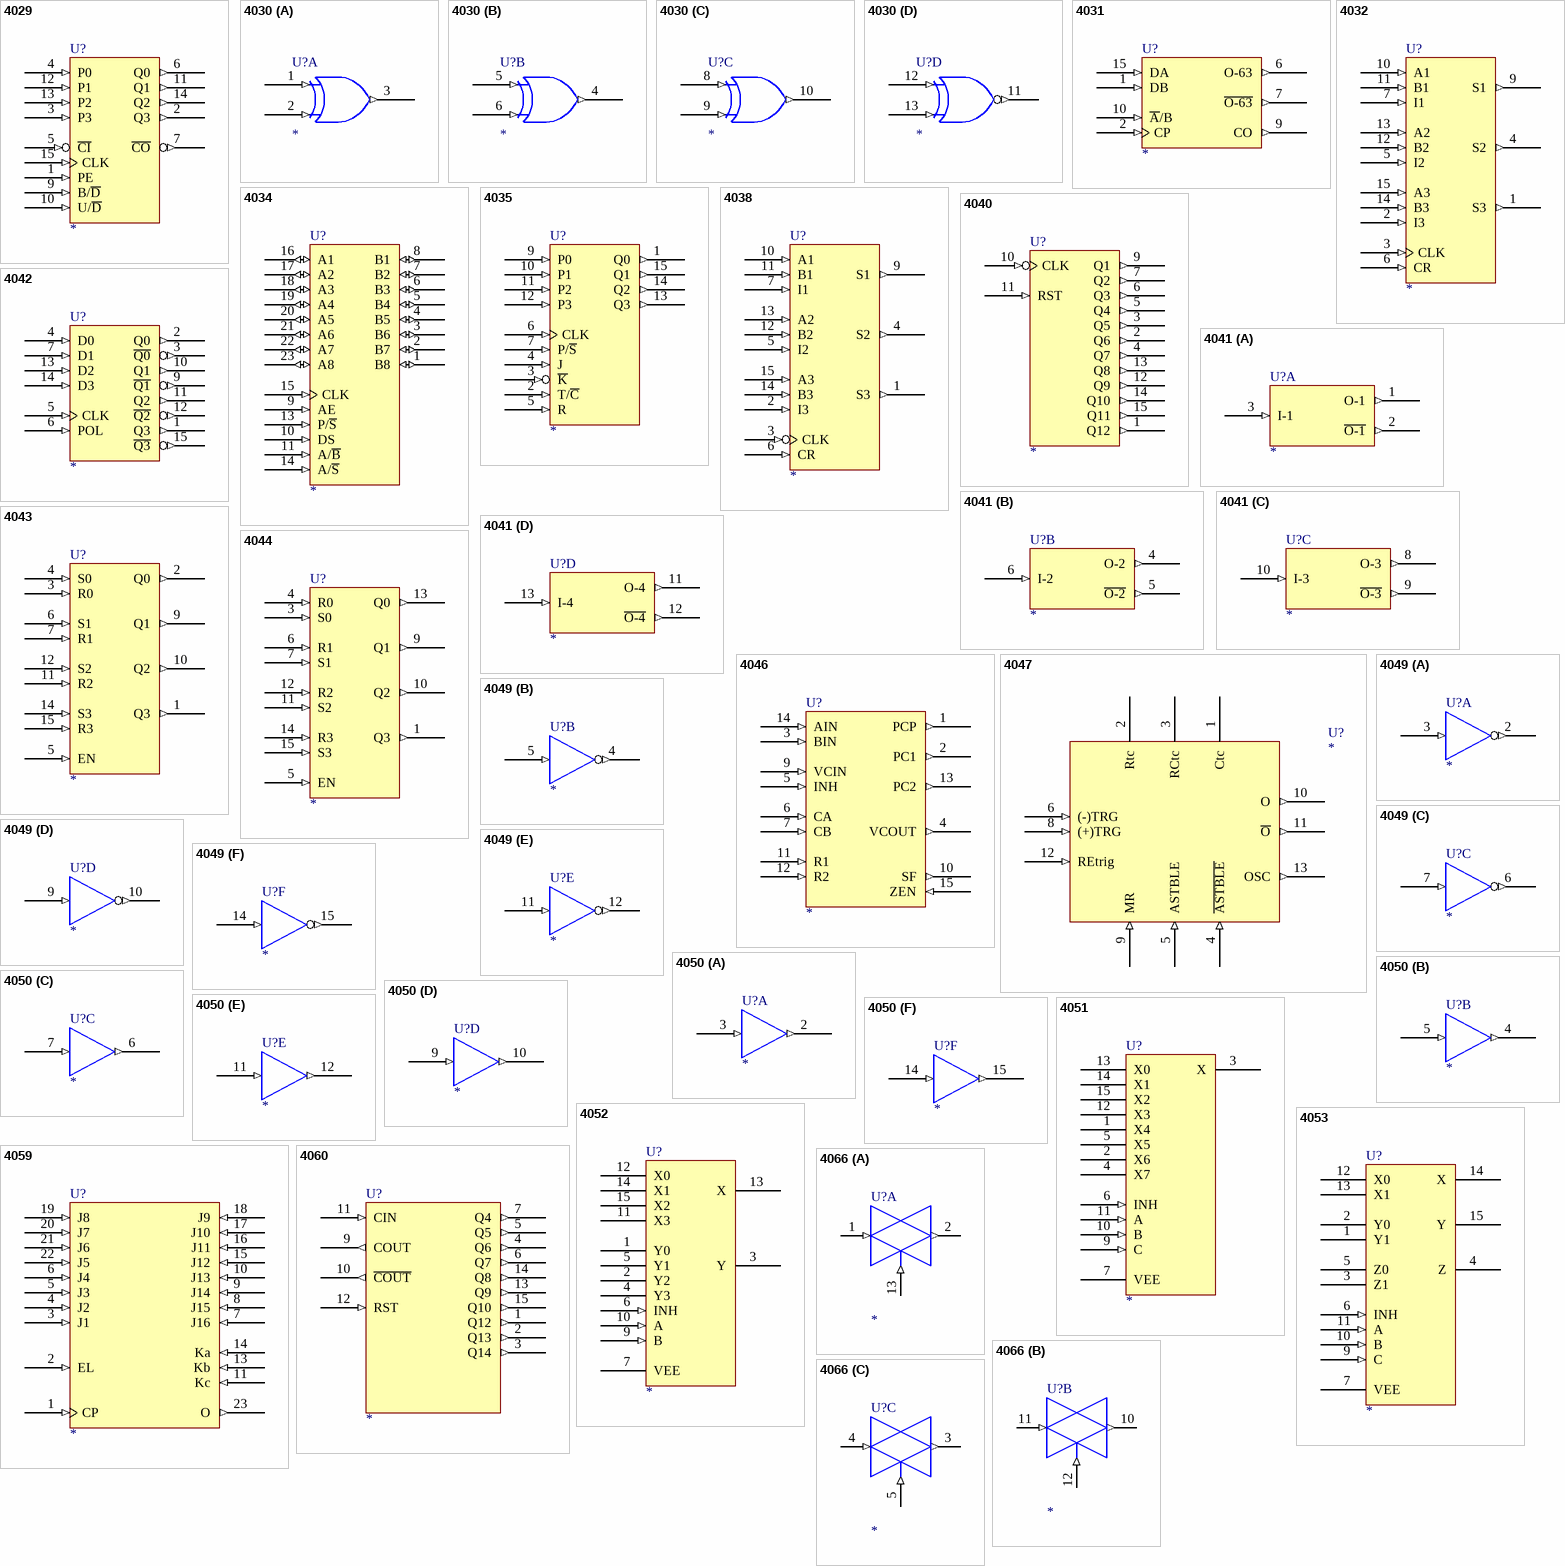
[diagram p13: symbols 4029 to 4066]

## 4029
designator U?
footprint DIP-16
pins: 1 PE (in), 2 Q3 (out), 3 P3 (in), 4 P0 (in), 5 ~{CI} (in), 6 Q0 (out), 7 ~{CO} (out), 8 GND (power) hidden to GND, 9 B/~{D} (in), 10 U/~{D} (in), 11 Q1 (out), 12 P1 (in), 13 P2 (in), 14 Q2 (out), 15 CLK (in), 16 VCC (power) hidden to VCC
2 alternate drawings of the same symbol

## 4030
designator U?
footprint DIP-14
part A pins: 1 (in), 2 (in), 3 (out), 7 GND (power) hidden to GND, 14 VCC (power) hidden to VCC
part B pins: 4 (out), 5 (in), 6 (in), 7 GND (power) hidden to GND, 14 VCC (power) hidden to VCC
part C pins: 7 GND (power) hidden to GND, 8 (in), 9 (in), 10 (out), 14 VCC (power) hidden to VCC
part D pins: 7 GND (power) hidden to GND, 11 (out), 12 (in), 13 (in), 14 VCC (power) hidden to VCC
2 alternate drawings of the same symbol

## 4031
designator U?
footprint DIP-16
pins: 1 DB (in), 2 CP (in), 6 O-63 (out), 7 ~{O-63} (out), 8 GND (power) hidden to GND, 9 CO (out), 10 ~{A}/B (in), 15 DA (in), 16 VCC (power) hidden to VCC
2 alternate drawings of the same symbol

## 4032
designator U?
footprint DIP-16
pins: 1 S3 (out), 2 I3 (in), 3 CLK (in), 4 S2 (out), 5 I2 (in), 6 CR (in), 7 I1 (in), 8 GND (power) hidden to GND, 9 S1 (out), 10 A1 (in), 11 B1 (in), 12 B2 (in), 13 A2 (in), 14 B3 (in), 15 A3 (in), 16 VCC (power) hidden to VCC
2 alternate drawings of the same symbol

## 4034
designator U?
footprint DIP-24
pins: 1 B8 (io), 2 B7 (io), 3 B6 (io), 4 B5 (io), 5 B4 (io), 6 B3 (io), 7 B2 (io), 8 B1 (io), 9 AE (in), 10 DS (in), 11 A/~{B} (in), 12 GND (power) hidden to GND, 13 P/~{S} (in), 14 A/~{S} (in), 15 CLK (in), 16 A1 (io), 17 A2 (io), 18 A3 (io), 19 A4 (io), 20 A5 (io), 21 A6 (io), 22 A7 (io), 23 A8 (io), 24 VCC (power) hidden to VCC
2 alternate drawings of the same symbol

## 4035
designator U?
footprint DIP-16
pins: 1 Q0 (out), 2 T/~{C} (in), 3 ~{K} (in), 4 J (in), 5 R (in), 6 CLK (in), 7 P/~{S} (in), 8 GND (power) hidden to GND, 9 P0 (in), 10 P1 (in), 11 P2 (in), 12 P3 (in), 13 Q3 (out), 14 Q2 (out), 15 Q1 (out), 16 VCC (power) hidden to VCC
2 alternate drawings of the same symbol

## 4038
designator U?
footprint DIP-16
pins: 1 S3 (out), 2 I3 (in), 3 CLK (in), 4 S2 (out), 5 I2 (in), 6 CR (in), 7 I1 (in), 8 GND (power) hidden to GND, 9 S1 (out), 10 A1 (in), 11 B1 (in), 12 B2 (in), 13 A2 (in), 14 B3 (in), 15 A3 (in), 16 VCC (power) hidden to VCC
2 alternate drawings of the same symbol

## 4040
designator U?
footprint DIP-16
pins: 1 Q12 (out), 2 Q6 (out), 3 Q5 (out), 4 Q7 (out), 5 Q4 (out), 6 Q3 (out), 7 Q2 (out), 8 GND (power) hidden to GND, 9 Q1 (out), 10 CLK (in), 11 RST (in), 12 Q9 (out), 13 Q8 (out), 14 Q10 (out), 15 Q11 (out), 16 VCC (power) hidden to VCC
2 alternate drawings of the same symbol

## 4041
designator U?
footprint DIP-14
part A pins: 1 O-1 (out), 2 ~{O-1} (out), 3 I-1 (in), 7 GND (power) hidden to GND, 14 VCC (power) hidden to VCC
part B pins: 4 O-2 (out), 5 ~{O-2} (out), 6 I-2 (in), 7 GND (power) hidden to GND, 14 VCC (power) hidden to VCC
part C pins: 7 GND (power) hidden to GND, 8 O-3 (out), 9 ~{O-3} (out), 10 I-3 (in), 14 VCC (power) hidden to VCC
part D pins: 7 GND (power) hidden to GND, 11 O-4 (out), 12 ~{O-4} (out), 13 I-4 (in), 14 VCC (power) hidden to VCC
2 alternate drawings of the same symbol

## 4042
designator U?
footprint DIP-16
pins: 1 Q3 (out), 2 Q0 (out), 3 ~{Q0} (out), 4 D0 (in), 5 CLK (in), 6 POL (in), 7 D1 (in), 8 GND (power) hidden to GND, 9 ~{Q1} (out), 10 Q1 (out), 11 Q2 (out), 12 ~{Q2} (out), 13 D2 (in), 14 D3 (in), 15 ~{Q3} (out), 16 VCC (power) hidden to VCC
2 alternate drawings of the same symbol

## 4043
designator U?
footprint DIP-16
pins: 1 Q3 (out), 2 Q0 (out), 3 R0 (in), 4 S0 (in), 5 EN (in), 6 S1 (in), 7 R1 (in), 8 GND (power) hidden to GND, 9 Q1 (out), 10 Q2 (out), 11 R2 (in), 12 S2 (in), 14 S3 (in), 15 R3 (in), 16 VCC (power) hidden to VCC
2 alternate drawings of the same symbol

## 4044
designator U?
footprint DIP-16
pins: 1 Q3 (out), 3 S0 (in), 4 R0 (in), 5 EN (in), 6 R1 (in), 7 S1 (in), 8 GND (power) hidden to GND, 9 Q1 (out), 10 Q2 (out), 11 S2 (in), 12 R2 (in), 13 Q0 (out), 14 R3 (in), 15 S3 (in), 16 VCC (power) hidden to VCC
2 alternate drawings of the same symbol

## 4046
designator U?
footprint DIP-16
pins: 1 PCP (out), 2 PC1 (out), 3 BIN (in), 4 VCOUT (out), 5 INH (in), 6 CA (in), 7 CB (in), 8 GND (power) hidden to GND, 9 VCIN (in), 10 SF (out), 11 R1 (in), 12 R2 (in), 13 PC2 (out), 14 AIN (in), 15 ZEN (in), 16 VCC (power) hidden to VCC
2 alternate drawings of the same symbol

## 4047
designator U?
footprint DIP-14
pins: 1 Ctc, 2 Rtc, 3 RCtc, 4 ~{ASTBLE} (in), 5 ASTBLE (in), 6 (-)TRG (in), 7 GND (power) hidden to GND, 8 (+)TRG (in), 9 MR (in), 10 O (out), 11 ~{O} (out), 12 REtrig (in), 13 OSC (out), 14 VCC (power) hidden to VCC
2 alternate drawings of the same symbol

## 4049
designator U?
footprint DIP-16
part A pins: 1 VCC (power) hidden to VCC, 2 (out), 3 (in), 8 GND (power) hidden to GND
part B pins: 1 VCC (power) hidden to VCC, 4 (out), 5 (in), 8 GND (power) hidden to GND
part C pins: 1 VCC (power) hidden to VCC, 6 (out), 7 (in), 8 GND (power) hidden to GND
part D pins: 1 VCC (power) hidden to VCC, 8 GND (power) hidden to GND, 9 (in), 10 (out)
part E pins: 1 VCC (power) hidden to VCC, 8 GND (power) hidden to GND, 11 (in), 12 (out)
part F pins: 1 VCC (power) hidden to VCC, 8 GND (power) hidden to GND, 14 (in), 15 (out)
2 alternate drawings of the same symbol

## 4050
designator U?
footprint DIP-16
part A pins: 1 VCC (power) hidden to VCC, 2 (out), 3 (in), 8 GND (power) hidden to GND
part B pins: 1 VCC (power) hidden to VCC, 4 (out), 5 (in), 8 GND (power) hidden to GND
part C pins: 1 VCC (power) hidden to VCC, 6 (out), 7 (in), 8 GND (power) hidden to GND
part D pins: 1 VCC (power) hidden to VCC, 8 GND (power) hidden to GND, 9 (in), 10 (out)
part E pins: 1 VCC (power) hidden to VCC, 8 GND (power) hidden to GND, 11 (in), 12 (out)
part F pins: 1 VCC (power) hidden to VCC, 8 GND (power) hidden to GND, 14 (in), 15 (out)
2 alternate drawings of the same symbol

## 4051
designator U?
footprint DIP-16
pins: 1 X4, 2 X6, 3 X, 4 X7, 5 X5, 6 INH (in), 7 VEE, 8 GND (power) hidden to GND, 9 C (in), 10 B (in), 11 A (in), 12 X3, 13 X0, 14 X1, 15 X2, 16 VCC (power) hidden to VCC
2 alternate drawings of the same symbol

## 4052
designator U?
footprint DIP16E
pins: 1 Y0, 2 Y2, 3 Y, 4 Y3, 5 Y1, 6 INH (in), 7 VEE, 8 GND (power) hidden to GND, 9 B (in), 10 A (in), 11 X3, 12 X0, 13 X, 14 X1, 15 X2, 16 VCC (power) hidden to VCC
2 alternate drawings of the same symbol

## 4053
designator U?
footprint DIP-16
pins: 1 Y1, 2 Y0, 3 Z1, 4 Z, 5 Z0, 6 INH (in), 7 VEE, 8 GND (power) hidden to GND, 9 C (in), 10 B (in), 11 A (in), 12 X0, 13 X1, 14 X, 15 Y, 16 VCC (power) hidden to VCC
2 alternate drawings of the same symbol

## 4059
designator U?
footprint DIP-24
pins: 1 CP (in), 2 EL (in), 3 J1 (in), 4 J2 (in), 5 J3 (in), 6 J4 (in), 7 J16 (in), 8 J15 (in), 9 J14 (in), 10 J13 (in), 11 Kc (in), 12 GND (power) hidden to GND, 13 Kb (in), 14 Ka (in), 15 J12 (in), 16 J11 (in), 17 J10 (in), 18 J9 (in), 19 J8 (in), 20 J7 (in), 21 J6 (in), 22 J5 (in), 23 O (out), 24 VCC (power) hidden to VCC
2 alternate drawings of the same symbol

## 4060
designator U?
footprint DIP-16
pins: 1 Q12 (out), 2 Q13 (out), 3 Q14 (out), 4 Q6 (out), 5 Q5 (out), 6 Q7 (out), 7 Q4 (out), 8 GND (power) hidden to GND, 9 COUT (out), 10 ~{COUT} (out), 11 CIN (in), 12 RST (in), 13 Q9 (out), 14 Q8 (out), 15 Q10 (out), 16 VCC (power) hidden to VCC
2 alternate drawings of the same symbol

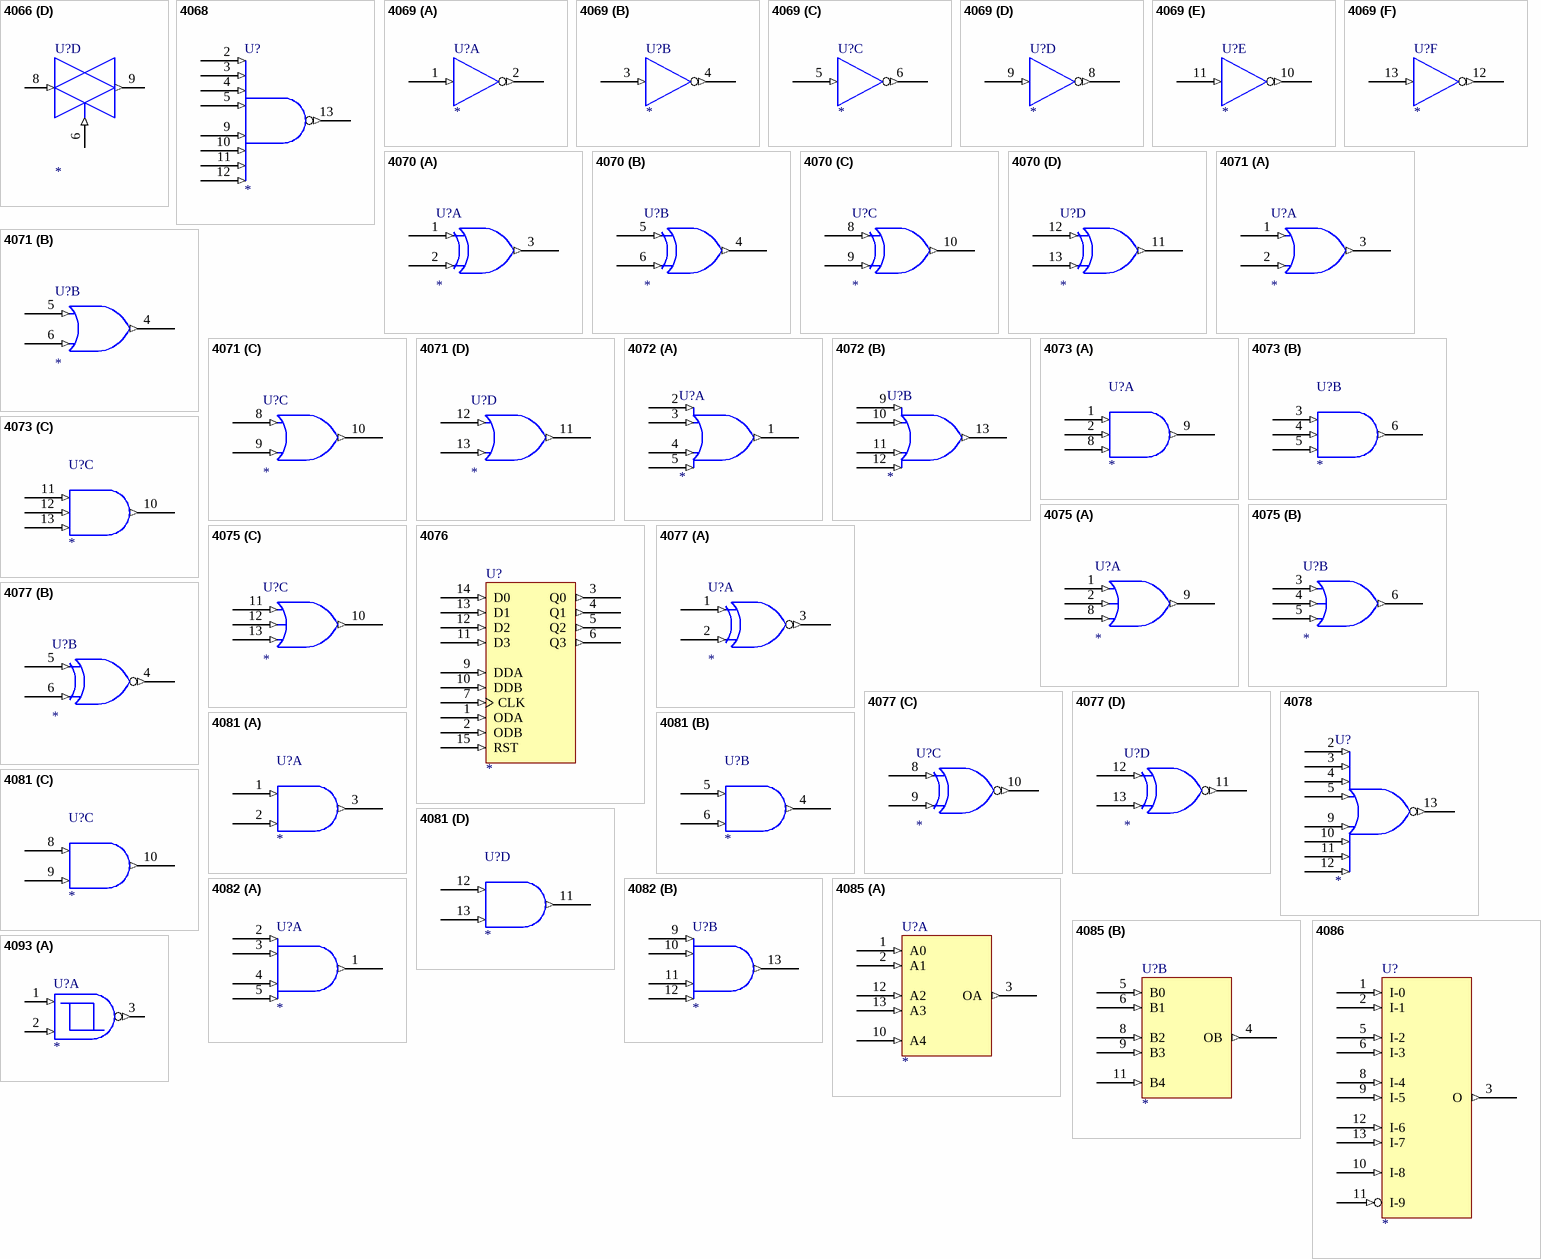
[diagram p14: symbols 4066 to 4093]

## 4066
designator U?
footprint DIP14E
part A pins: 1 (in), 2 (out), 7 GND (power) hidden to GND, 13 (in), 14 VCC (power) hidden to VCC
part B pins: 7 GND (power) hidden to GND, 10 (out), 11 (in), 12 (in), 14 VCC (power) hidden to VCC
part C pins: 3 (out), 4 (in), 5 (in), 7 GND (power) hidden to GND, 14 VCC (power) hidden to VCC
part D pins: 6 (in), 7 GND (power) hidden to GND, 8 (in), 9 (out), 14 VCC (power) hidden to VCC
2 alternate drawings of the same symbol

## 4068
designator U?
footprint DIP-14
pins: 2 (in), 3 (in), 4 (in), 5 (in), 7 GND (power) hidden to GND, 9 (in), 10 (in), 11 (in), 12 (in), 13 (out), 14 VCC (power) hidden to VCC
2 alternate drawings of the same symbol

## 4069
designator U?
footprint DIP14E
footprint DIP-14
part A pins: 1 (in), 2 (out), 7 GND (power) hidden to GND, 14 VCC (power) hidden to VCC
part B pins: 3 (in), 4 (out), 7 GND (power) hidden to GND, 14 VCC (power) hidden to VCC
part C pins: 5 (in), 6 (out), 7 GND (power) hidden to GND, 14 VCC (power) hidden to VCC
part D pins: 7 GND (power) hidden to GND, 8 (out), 9 (in), 14 VCC (power) hidden to VCC
part E pins: 7 GND (power) hidden to GND, 10 (out), 11 (in), 14 VCC (power) hidden to VCC
part F pins: 7 GND (power) hidden to GND, 12 (out), 13 (in), 14 VCC (power) hidden to VCC
2 alternate drawings of the same symbol

## 4070
designator U?
footprint DIP-14
part A pins: 1 (in), 2 (in), 3 (out), 7 GND (power) hidden to GND, 14 VCC (power) hidden to VCC
part B pins: 4 (out), 5 (in), 6 (in), 7 GND (power) hidden to GND, 14 VCC (power) hidden to VCC
part C pins: 7 GND (power) hidden to GND, 8 (in), 9 (in), 10 (out), 14 VCC (power) hidden to VCC
part D pins: 7 GND (power) hidden to GND, 11 (out), 12 (in), 13 (in), 14 VCC (power) hidden to VCC
2 alternate drawings of the same symbol

## 4071
designator U?
footprint DIP-14
part A pins: 1 (in), 2 (in), 3 (out), 7 GND (power) hidden to GND, 14 VCC (power) hidden to VCC
part B pins: 4 (out), 5 (in), 6 (in), 7 GND (power) hidden to GND, 14 VCC (power) hidden to VCC
part C pins: 7 GND (power) hidden to GND, 8 (in), 9 (in), 10 (out), 14 VCC (power) hidden to VCC
part D pins: 7 GND (power) hidden to GND, 11 (out), 12 (in), 13 (in), 14 VCC (power) hidden to VCC
2 alternate drawings of the same symbol

## 4072
designator U?
footprint DIP-14
part A pins: 1 (out), 2 (in), 3 (in), 4 (in), 5 (in), 7 GND (power) hidden to GND, 14 VCC (power) hidden to VCC
part B pins: 7 GND (power) hidden to GND, 9 (in), 10 (in), 11 (in), 12 (in), 13 (out), 14 VCC (power) hidden to VCC
2 alternate drawings of the same symbol

## 4073
designator U?
footprint DIP-14
part A pins: 1 (in), 2 (in), 7 GND (power) hidden to GND, 8 (in), 9 (out), 14 VCC (power) hidden to VCC
part B pins: 3 (in), 4 (in), 5 (in), 6 (out), 7 GND (power) hidden to GND, 14 VCC (power) hidden to VCC
part C pins: 7 GND (power) hidden to GND, 10 (out), 11 (in), 12 (in), 13 (in), 14 VCC (power) hidden to VCC
2 alternate drawings of the same symbol

## 4075
designator U?
footprint DIP-14
part A pins: 1 (in), 2 (in), 7 GND (power) hidden to GND, 8 (in), 9 (out), 14 VCC (power) hidden to VCC
part B pins: 3 (in), 4 (in), 5 (in), 6 (out), 7 GND (power) hidden to GND, 14 VCC (power) hidden to VCC
part C pins: 7 GND (power) hidden to GND, 10 (out), 11 (in), 12 (in), 13 (in), 14 VCC (power) hidden to VCC
2 alternate drawings of the same symbol

## 4076
designator U?
footprint DIP-16
pins: 1 ODA (in), 2 ODB (in), 3 Q0 (out), 4 Q1 (out), 5 Q2 (out), 6 Q3 (out), 7 CLK (in), 8 GND (power) hidden to GND, 9 DDA (in), 10 DDB (in), 11 D3 (in), 12 D2 (in), 13 D1 (in), 14 D0 (in), 15 RST (in), 16 VCC (power) hidden to VCC
2 alternate drawings of the same symbol

## 4077
designator U?
footprint DIP-14
part A pins: 1 (in), 2 (in), 3 (out), 7 GND (power) hidden to GND, 14 VCC (power) hidden to VCC
part B pins: 4 (out), 5 (in), 6 (in), 7 GND (power) hidden to GND, 14 VCC (power) hidden to VCC
part C pins: 7 GND (power) hidden to GND, 8 (in), 9 (in), 10 (out), 14 VCC (power) hidden to VCC
part D pins: 7 GND (power) hidden to GND, 11 (out), 12 (in), 13 (in), 14 VCC (power) hidden to VCC
2 alternate drawings of the same symbol

## 4078
designator U?
footprint DIP-14
pins: 2 (in), 3 (in), 4 (in), 5 (in), 7 GND (power) hidden to GND, 9 (in), 10 (in), 11 (in), 12 (in), 13 (out), 14 VCC (power) hidden to VCC
2 alternate drawings of the same symbol

## 4081
designator U?
footprint DIP-14
part A pins: 1 (in), 2 (in), 3 (out), 7 GND (power) hidden to GND, 14 VCC (power) hidden to VCC
part B pins: 4 (out), 5 (in), 6 (in), 7 GND (power) hidden to GND, 14 VCC (power) hidden to VCC
part C pins: 7 GND (power) hidden to GND, 8 (in), 9 (in), 10 (out), 14 VCC (power) hidden to VCC
part D pins: 7 GND (power) hidden to GND, 11 (out), 12 (in), 13 (in), 14 VCC (power) hidden to VCC
2 alternate drawings of the same symbol

## 4082
designator U?
footprint DIP-14
part A pins: 1 (out), 2 (in), 3 (in), 4 (in), 5 (in), 7 GND (power) hidden to GND, 14 VCC (power) hidden to VCC
part B pins: 7 GND (power) hidden to GND, 9 (in), 10 (in), 11 (in), 12 (in), 13 (out), 14 VCC (power) hidden to VCC
2 alternate drawings of the same symbol

## 4085
designator U?
footprint DIP-14
part A pins: 1 A0 (in), 2 A1 (in), 3 OA (out), 7 GND (power) hidden to GND, 10 A4 (in), 12 A2 (in), 13 A3 (in), 14 VCC (power) hidden to VCC
part B pins: 4 OB (out), 5 B0 (in), 6 B1 (in), 7 GND (power) hidden to GND, 8 B2 (in), 9 B3 (in), 11 B4 (in), 14 VCC (power) hidden to VCC
2 alternate drawings of the same symbol

## 4086
designator U?
footprint DIP-14
pins: 1 I-0 (in), 2 I-1 (in), 3 O (out), 5 I-2 (in), 6 I-3 (in), 7 GND (power) hidden to GND, 8 I-4 (in), 9 I-5 (in), 10 I-8 (in), 11 I-9 (in), 12 I-6 (in), 13 I-7 (in), 14 VCC (power) hidden to VCC
2 alternate drawings of the same symbol

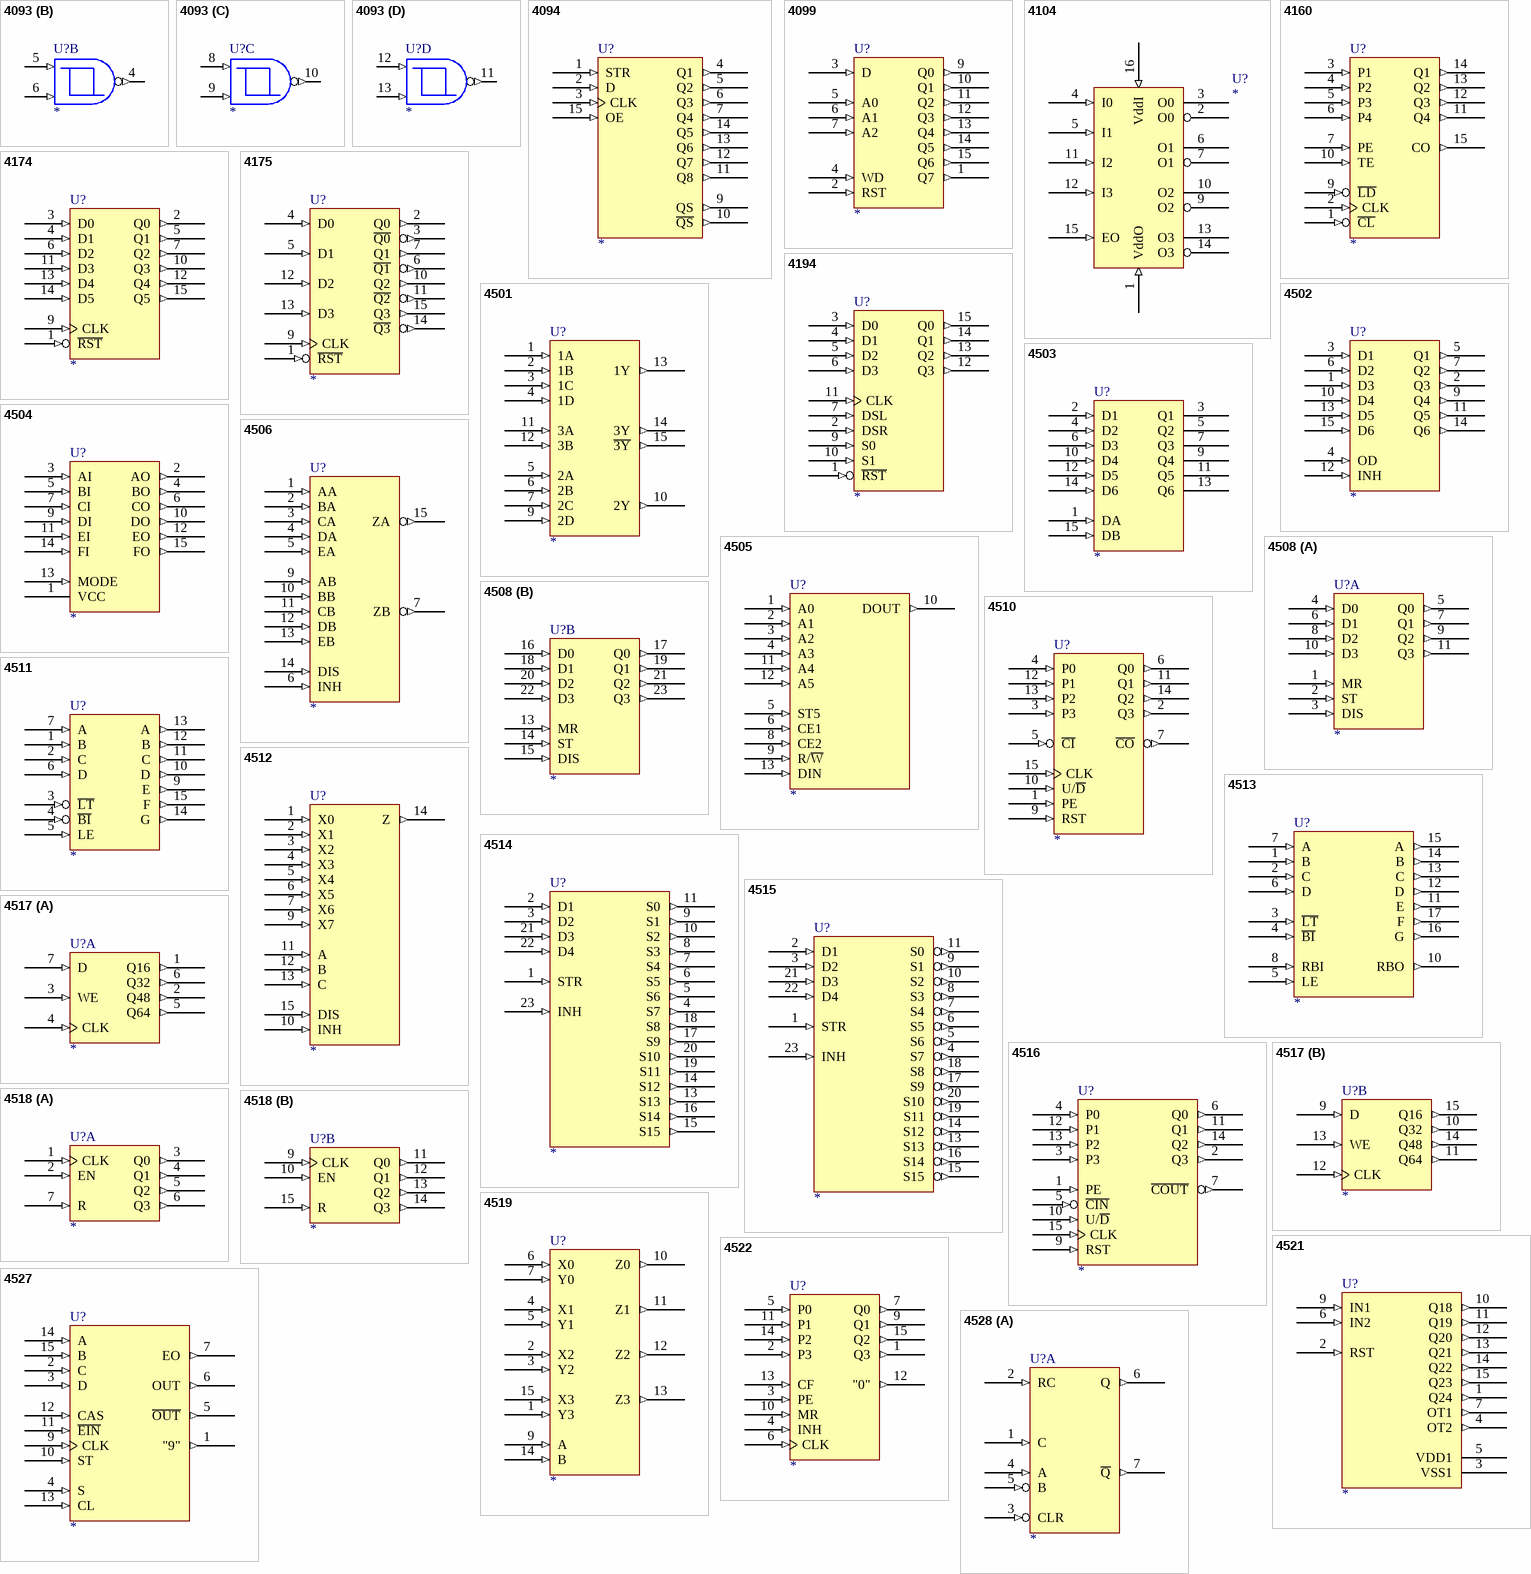
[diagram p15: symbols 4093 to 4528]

## 4093
designator U?
footprint DIP14E
part A pins: 1 (in), 2 (in), 3 (out), 7 GND (power) hidden to GND, 14 VCC (power) hidden to VCC
part B pins: 4 (out), 5 (in), 6 (in), 7 GND (power) hidden to GND, 14 VCC (power) hidden to VCC
part C pins: 7 GND (power) hidden to GND, 8 (in), 9 (in), 10 (out), 14 VCC (power) hidden to VCC
part D pins: 7 GND (power) hidden to GND, 11 (out), 12 (in), 13 (in), 14 VCC (power) hidden to VCC
2 alternate drawings of the same symbol

## 4094
designator U?
footprint DIP-16
pins: 1 STR (in), 2 D (in), 3 CLK (in), 4 Q1 (out), 5 Q2 (out), 6 Q3 (out), 7 Q4 (out), 8 GND (power) hidden to GND, 9 QS (out), 10 ~{QS} (out), 11 Q8 (out), 12 Q7 (out), 13 Q6 (out), 14 Q5 (out), 15 OE (in), 16 VCC (power) hidden to VCC
2 alternate drawings of the same symbol

## 4099
designator U?
footprint DIP-16
pins: 1 Q7 (out), 2 RST (in), 3 D (in), 4 WD (in), 5 A0 (in), 6 A1 (in), 7 A2 (in), 8 GND (power) hidden to GND, 9 Q0 (out), 10 Q1 (out), 11 Q2 (out), 12 Q3 (out), 13 Q4 (out), 14 Q5 (out), 15 Q6 (out), 16 VCC (power) hidden to VCC
2 alternate drawings of the same symbol

## 4104
designator U?
footprint DIP-16
pins: 1 VddO (in), 2 O0 (hiz), 3 O0 (hiz), 4 I0 (in), 5 I1 (in), 6 O1 (hiz), 7 O1 (hiz), 8 GND (power) hidden to GND, 9 O2 (hiz), 10 O2 (hiz), 11 I2 (in), 12 I3 (in), 13 O3 (hiz), 14 O3 (hiz), 15 EO (in), 16 VddI (in)
2 alternate drawings of the same symbol

## 4160
designator U?
footprint DIP-16
pins: 1 ~{CL} (in), 2 CLK (in), 3 P1 (in), 4 P2 (in), 5 P3 (in), 6 P4 (in), 7 PE (in), 8 GND (power) hidden to GND, 9 ~{LD} (in), 10 TE (in), 11 Q4 (out), 12 Q3 (out), 13 Q2 (out), 14 Q1 (out), 15 CO (out), 16 VCC (power) hidden to VCC
2 alternate drawings of the same symbol

## 4174
designator U?
footprint DIP-16
pins: 1 ~{RST} (in), 2 Q0 (out), 3 D0 (in), 4 D1 (in), 5 Q1 (out), 6 D2 (in), 7 Q2 (out), 8 GND (power) hidden to GND, 9 CLK (in), 10 Q3 (out), 11 D3 (in), 12 Q4 (out), 13 D4 (in), 14 D5 (in), 15 Q5 (out), 16 VCC (power) hidden to VCC
2 alternate drawings of the same symbol

## 4175
designator U?
footprint DIP-16
pins: 1 ~{RST} (in), 2 Q0 (out), 3 ~{Q0} (out), 4 D0 (in), 5 D1 (in), 6 ~{Q1} (out), 7 Q1 (out), 8 GND (power) hidden to GND, 9 CLK (in), 10 Q2 (out), 11 ~{Q2} (out), 12 D2 (in), 13 D3 (in), 14 ~{Q3} (out), 15 Q3 (out), 16 VCC (power) hidden to VCC
2 alternate drawings of the same symbol

## 4194
designator U?
footprint DIP-16
pins: 1 ~{RST} (in), 2 DSR (in), 3 D0 (in), 4 D1 (in), 5 D2 (in), 6 D3 (in), 7 DSL (in), 8 GND (power) hidden to GND, 9 S0 (in), 10 S1 (in), 11 CLK (in), 12 Q3 (out), 13 Q2 (out), 14 Q1 (out), 15 Q0 (out), 16 VCC (power) hidden to VCC
2 alternate drawings of the same symbol

## 4501
designator U?
footprint DIP-16
pins: 1 1A (in), 2 1B (in), 3 1C (in), 4 1D (in), 5 2A (in), 6 2B (in), 7 2C (in), 8 GND (power) hidden to GND, 9 2D (in), 10 2Y (out), 11 3A (in), 12 3B (in), 13 1Y (out), 14 3Y (out), 15 ~{3Y} (out), 16 VCC (power) hidden to VCC
2 alternate drawings of the same symbol

## 4502
designator U?
footprint DIP-16
pins: 1 D3 (in), 2 Q3 (out), 3 D1 (in), 4 OD (in), 5 Q1 (out), 6 D2 (in), 7 Q2 (out), 8 GND (power) hidden to GND, 9 Q4 (out), 10 D4 (in), 11 Q5 (out), 12 INH (in), 13 D5 (in), 14 Q6 (out), 15 D6 (in), 16 VCC (power) hidden to VCC
2 alternate drawings of the same symbol

## 4503
designator U?
footprint DIP-16
pins: 1 DA (in), 2 D1 (in), 3 Q1 (hiz), 4 D2 (in), 5 Q2 (hiz), 6 D3 (in), 7 Q3 (hiz), 8 GND (power) hidden to GND, 9 Q4 (hiz), 10 D4 (in), 11 Q5 (hiz), 12 D5 (in), 13 Q6 (hiz), 14 D6 (in), 15 DB (in), 16 VCC (power) hidden to VCC
2 alternate drawings of the same symbol

## 4504
designator U?
footprint DIP-16
pins: 1 VCC (power), 2 AO (out), 3 AI (in), 4 BO (out), 5 BI (in), 6 CO (out), 7 CI (in), 8 GND (power) hidden to GND, 9 DI (in), 10 DO (out), 11 EI (in), 12 EO (out), 13 MODE (in), 14 FI (in), 15 FO (out), 16 VCC (power) hidden to VCC
2 alternate drawings of the same symbol

## 4505
designator U?
footprint DIP-14
pins: 1 A0 (in), 2 A1 (in), 3 A2 (in), 4 A3 (in), 5 ST5 (in), 6 CE1 (in), 7 GND (power) hidden to GND, 8 CE2 (in), 9 R/~{W} (in), 10 DOUT (out), 11 A4 (in), 12 A5 (in), 13 DIN (in), 14 VCC (power) hidden to VCC
2 alternate drawings of the same symbol

## 4506
designator U?
footprint DIP-16
pins: 1 AA (in), 2 BA (in), 3 CA (in), 4 DA (in), 5 EA (in), 6 INH (in), 7 ZB (out), 8 GND (power) hidden to GND, 9 AB (in), 10 BB (in), 11 CB (in), 12 DB (in), 13 EB (in), 14 DIS (in), 15 ZA (out), 16 VCC (power) hidden to VCC
2 alternate drawings of the same symbol

## 4508
designator U?
footprint DIP-24
part A pins: 1 MR (in), 2 ST (in), 3 DIS (in), 4 D0 (in), 5 Q0 (out), 6 D1 (in), 7 Q1 (out), 8 D2 (in), 9 Q2 (out), 10 D3 (in), 11 Q3 (out), 12 GND (power) hidden to GND, 24 VCC (power) hidden to VCC
part B pins: 12 GND (power) hidden to GND, 13 MR (in), 14 ST (in), 15 DIS (in), 16 D0 (in), 17 Q0 (out), 18 D1 (in), 19 Q1 (out), 20 D2 (in), 21 Q2 (out), 22 D3 (in), 23 Q3 (out), 24 VCC (power) hidden to VCC
2 alternate drawings of the same symbol

## 4510
designator U?
footprint DIP-16
pins: 1 PE (in), 2 Q3 (out), 3 P3 (in), 4 P0 (in), 5 ~{CI} (in), 6 Q0 (out), 7 ~{CO} (out), 8 GND (power) hidden to GND, 9 RST (in), 10 U/~{D} (in), 11 Q1 (out), 12 P1 (in), 13 P2 (in), 14 Q2 (out), 15 CLK (in), 16 VCC (power) hidden to VCC
2 alternate drawings of the same symbol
